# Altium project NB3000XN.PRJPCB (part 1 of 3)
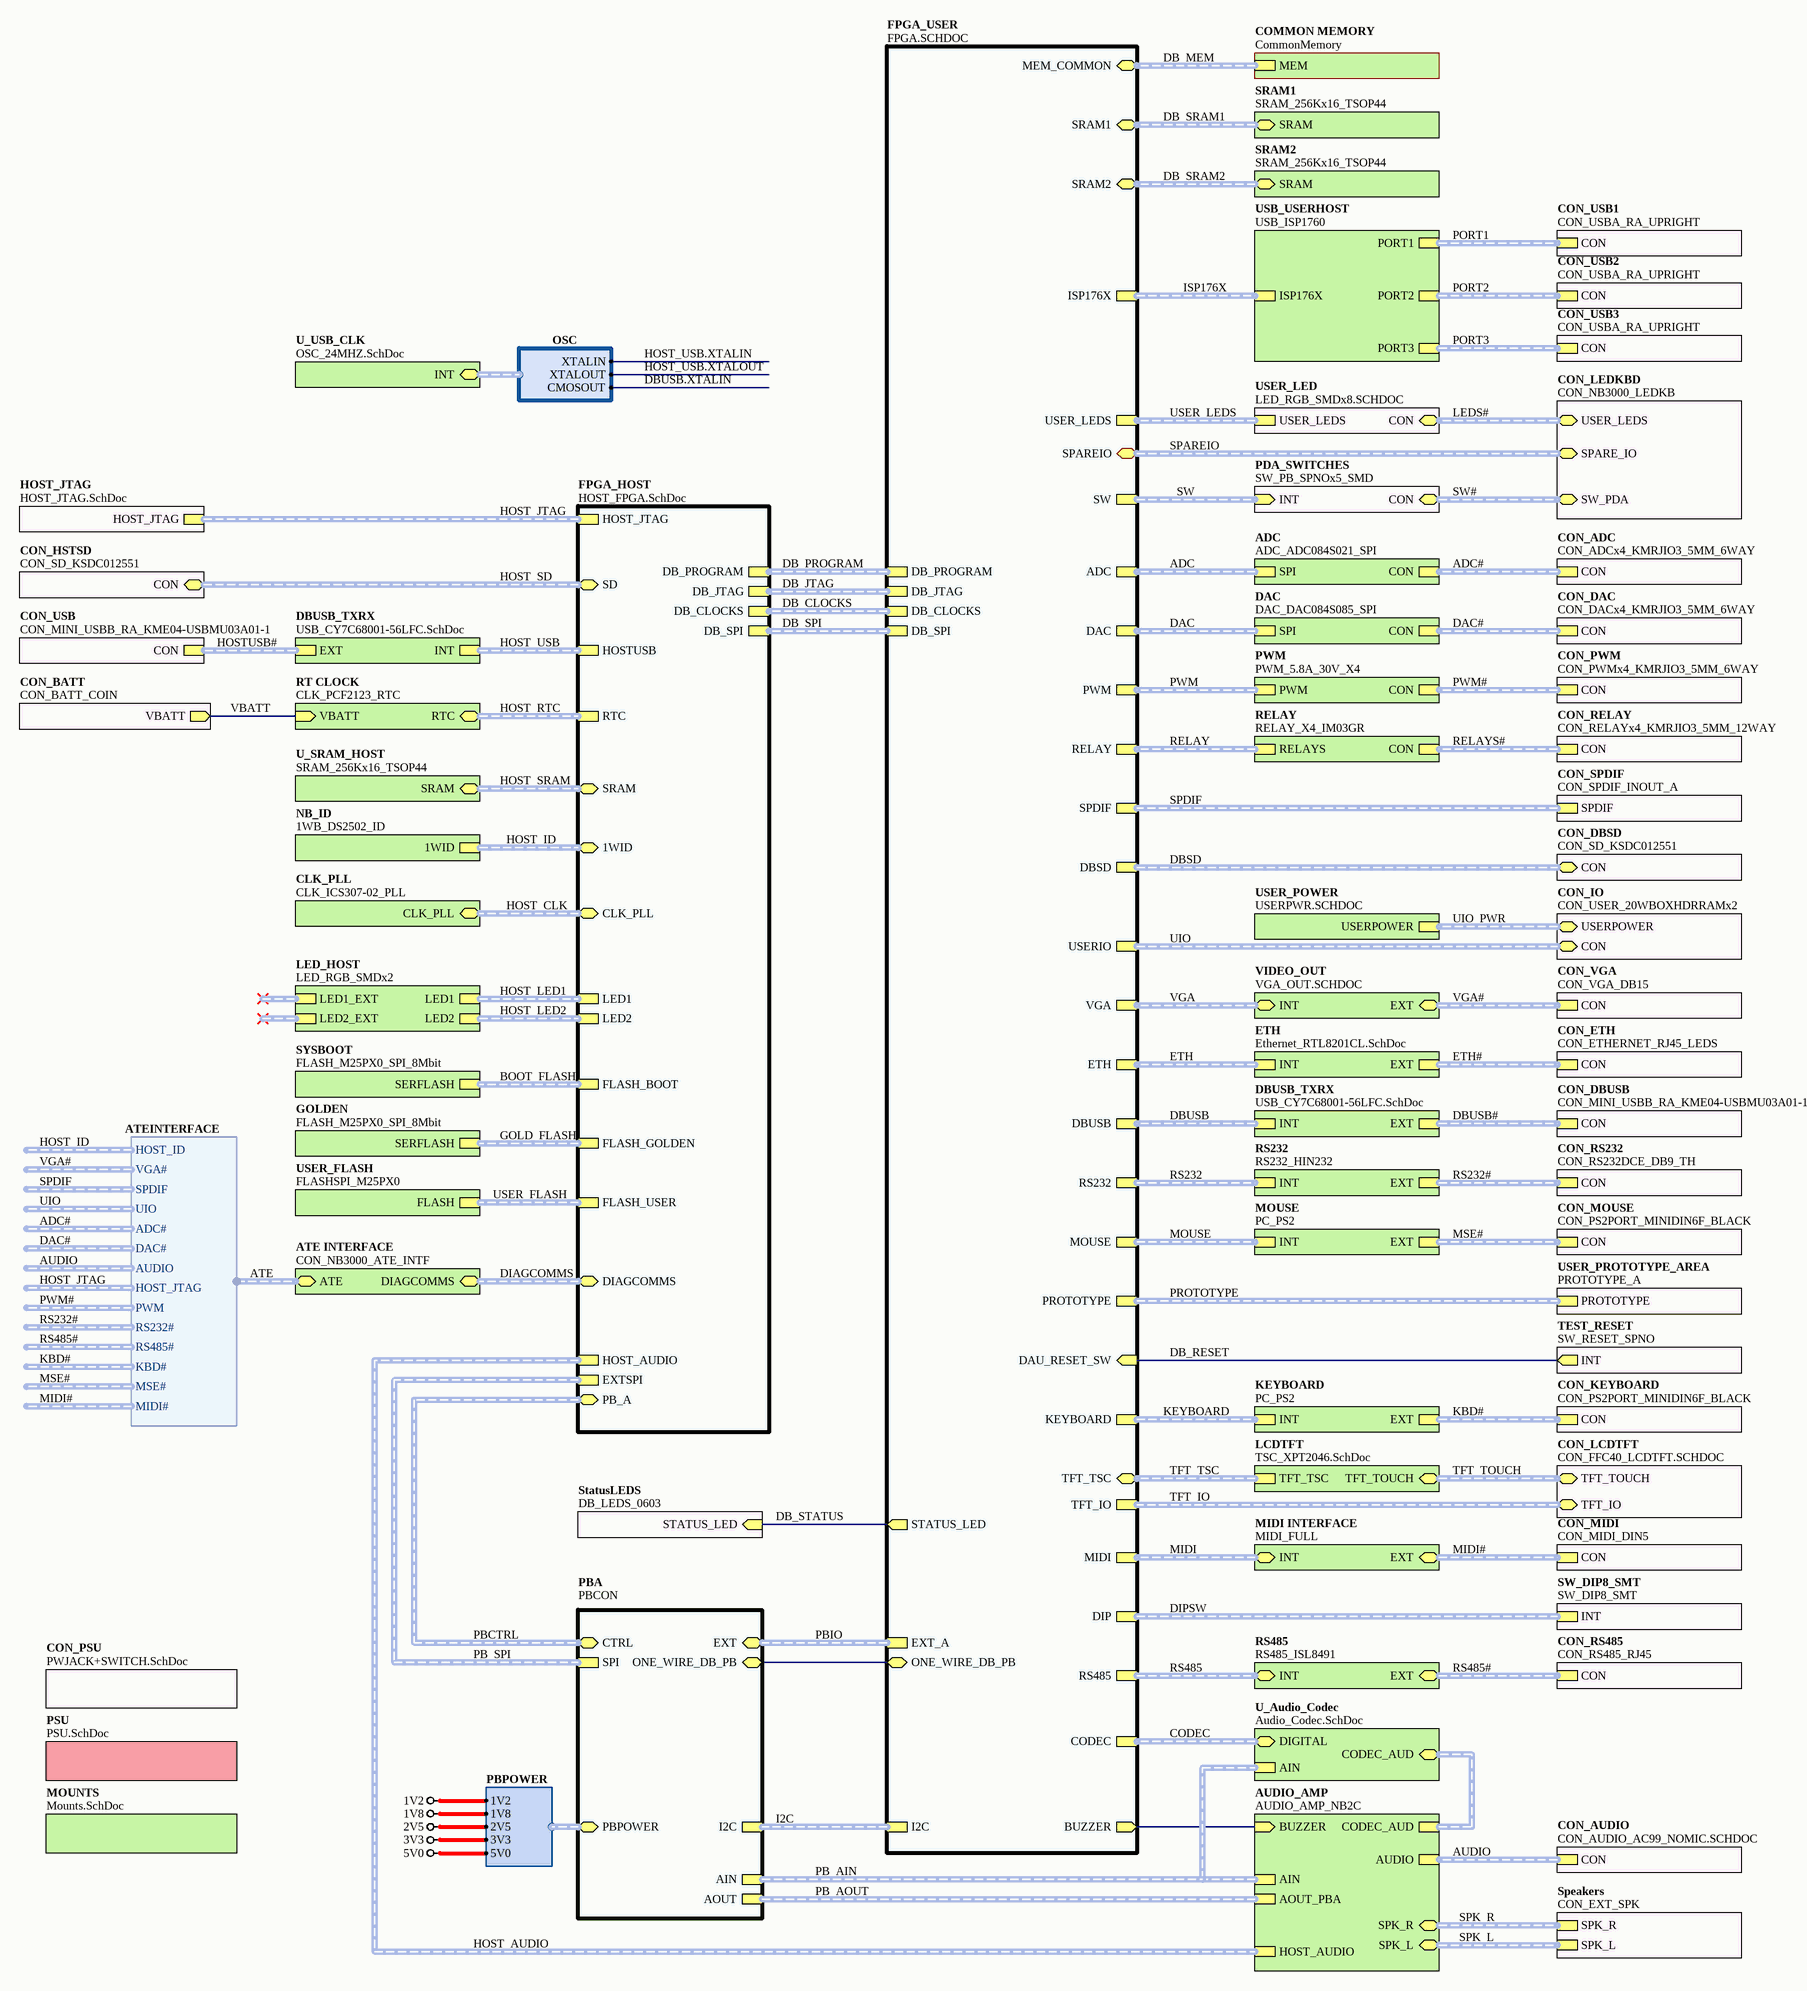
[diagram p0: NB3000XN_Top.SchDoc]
ProjectAddress1: 3 Minna Close; ProjectAddress2: Belrose; ProjectAddress3: NSW 2085; ProjectAddress4: Australia; ProjectAssyNum: TBA; ProjectOrganization: Altium Limited; ProjectRevision: 04; ProjectTitle: NB3000XN - Xilinx; ProjectTotalSheets: 106
22 sheets, 343 parts. Net scope: hierarchical (ports join the sheet entries above them; power ports are global).
Board files: NB3000XN.PcbDoc, NB3000XN_Panel.PcbDoc
Sheets:
  NB3000XN_Top.SchDoc
    PSU = PSU.SchDoc
    FPGA_USER = FPGA.SCHDOC
      U_FPGA_Power = FPGA_NonIO.SchDoc
      USER_DECOUPLING_CAPS_1V2 = FPGA_Bypass_1V2.SCHDOC
      USER_DECOUPLING_CAPS_3V3 = FPGA_Bypass_3V3.SCHDOC
    VIDEO_OUT = VGA_OUT.SCHDOC
      U_VIDEO_DAC = VIDEO_DAC_THS8134B.SchDoc
    FPGA_HOST = Host_FPGA.SchDoc
      HOST_NonIO = HOST_FPGA_NonIO.SchDoc
      HOST_DECOUPLING_CAPS_1V2 = FPGA_Bypass_1V2.SCHDOC
      HOST_DECOUPLING_CAPS_3V3 = FPGA_Bypass_3V3.SCHDOC
    HOST_JTAG = HOST_JTAG.SchDoc
    DBUSB_TXRX = USB_CY7C68001-56LFC.SchDoc
    ETH = Ethernet_RTL8201CL.SchDoc
    LCDTFT = TSC_XPT2046.SchDoc
    USER_LED = LED_RGB_SMDx8.SCHDOC
    U_Audio_Codec = Audio_Codec.SchDoc
    CON_LCDTFT = CON_FFC40_LCDTFT.SCHDOC
    MOUNTS = Mounts.SchDoc
    CON_PSU = PWJACK+SWITCH.SchDoc
    DBUSB_TXRX = USB_CY7C68001-56LFC.SchDoc
    USER_POWER = USERPWR.SchDoc
    CON_AUDIO = CON_AUDIO_AC99_NOMIC.SchDoc
    U_USB_CLK = OSC_24MHZ.SchDoc

## Sheet NB3000XN_Top.SchDoc: NB3000XN Top Level
size A2; Revision: 5; SheetNumber: 1; SheetTotal: 106; Organization: Altium Limited.; Address1: Level 3, 12a Rodborough Rd; Address2: Frenchs Forest 2086; Address3: NSW; Address4: AUSTRALIA

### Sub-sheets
ADC = ADC_ADC084S021_SPI (file not in this document): SPI (harness ADC_SPI), CON (harness ADC_CON)
ATE INTERFACE = CON_NB3000_ATE_INTF (file not in this document): ATE (harness ATEINTERFACE), DIAGCOMMS (harness DIAGCOMMS)
AUDIO_AMP = AUDIO_AMP_NB2C (file not in this document): BUZZER (in), CODEC_AUD (harness STEREO), AUDIO (harness AUDIO_EXT), SPK_L (harness SPEAKER), SPK_R (harness SPEAKER), HOST_AUDIO (harness STEREO), AIN (harness AUDIO_IN), AOUT_PBA (harness AUDIO_OUT)
CLK_PLL = CLK_ICS307-02_PLL (file not in this document): CLK_PLL (harness CLK_PLL)
COMMON MEMORY = CommonMemory (file not in this document): MEM (harness HOSTMEMORY)
CON_ADC = CON_ADCx4_KMRJIO3_5MM_6WAY (file not in this document): CON (harness ADC_CON)
CON_AUDIO = CON_AUDIO_AC99_NOMIC.SCHDOC: CON (harness AUDIO_EXT)
CON_BATT = CON_BATT_COIN (file not in this document): VBATT (out)
CON_DAC = CON_DACx4_KMRJIO3_5MM_6WAY (file not in this document): CON (harness DAC_CON)
CON_DBSD = CON_SD_KSDC012551 (file not in this document): CON (harness SD)
CON_DBUSB = CON_MINI_USBB_RA_KME04-USBMU03A01-1 (file not in this document): CON (harness USB_CON)
CON_ETH = CON_ETHERNET_RJ45_LEDS (file not in this document): CON (harness ETHERNET_CON)
CON_HSTSD = CON_SD_KSDC012551 (file not in this document): CON (harness SD)
CON_IO = CON_USER_20WBOXHDRRAMx2 (file not in this document): CON (harness IO36), USERPOWER (harness USERPOWER)
CON_KEYBOARD = CON_PS2PORT_MINIDIN6F_BLACK (file not in this document): CON (harness PS2)
CON_LCDTFT = CON_FFC40_LCDTFT.SCHDOC: TFT_IO (harness TFT_IO), TFT_TOUCH (harness TFT_TOUCH)
CON_LEDKBD = CON_NB3000_LEDKB (file not in this document): USER_LEDS (harness User_LEDS), SW_PDA (harness SW5), SPARE_IO (harness SPAREIO)
CON_MIDI = CON_MIDI_DIN5 (file not in this document): CON (harness MIDI_IO)
CON_MOUSE = CON_PS2PORT_MINIDIN6F_BLACK (file not in this document): CON (harness PS2)
CON_PSU = PWJACK+SWITCH.SchDoc: no entries
CON_PWM = CON_PWMx4_KMRJIO3_5MM_6WAY (file not in this document): CON (harness PWM_CON)
CON_RELAY = CON_RELAYx4_KMRJIO3_5MM_12WAY (file not in this document): CON (harness RELAY_CON4)
CON_RS232 = CON_RS232DCE_DB9_TH (file not in this document): CON (harness RS232_EXT)
CON_RS485 = CON_RS485_RJ45 (file not in this document): CON (harness RS485_EXT)
CON_SPDIF = CON_SPDIF_INOUT_A (file not in this document): SPDIF (harness SPDIF)
CON_USB = CON_MINI_USBB_RA_KME04-USBMU03A01-1 (file not in this document): CON (harness USB_CON)
CON_USB1 = CON_USBA_RA_UPRIGHT (file not in this document): CON (harness USB_CON)
CON_USB2 = CON_USBA_RA_UPRIGHT (file not in this document): CON (harness USB_CON)
CON_USB3 = CON_USBA_RA_UPRIGHT (file not in this document): CON (harness USB_CON)
CON_VGA = CON_VGA_DB15 (file not in this document): CON (harness VGA_CON)
DAC = DAC_DAC084S085_SPI (file not in this document): SPI (harness DAC_SPI), CON (harness DAC_CON)
DBUSB_TXRX = USB_CY7C68001-56LFC.SchDoc: EXT (harness USB_CON), INT (harness USB_INTF)
DBUSB_TXRX = USB_CY7C68001-56LFC.SchDoc: EXT (harness USB_CON), INT (harness USB_INTF)
ETH = Ethernet_RTL8201CL.SchDoc: INT (harness Ethernet), EXT (harness ETHERNET_CON)
FPGA_HOST = HOST_FPGA.SchDoc: HOST_JTAG (harness HARDSOFT_JTAG), LED1 (harness RGB_LED), LED2 (harness RGB_LED), 1WID (harness 1W), DB_PROGRAM (harness DAU_CTRL), CLK_PLL (harness CLK_PLL), FLASH_BOOT (harness SERFLASH), HOSTUSB (harness USB_INTF), SRAM (harness SRAM-256Kx16), RTC (harness RTC), SD (harness SD), HOST_AUDIO (harness STEREO), DB_JTAG (harness HARDSOFT_JTAG), DB_CLOCKS (harness DB_CLOCKS), FLASH_USER (harness SERIALFLASH), DB_SPI (harness DB_SPI), PB_A (harness PBCTRL), EXTSPI (harness EXTSPI), FLASH_GOLDEN (harness SERFLASH), DIAGCOMMS (harness DIAGCOMMS)
FPGA_USER = FPGA.SCHDOC: SRAM1 (harness SRAM-256Kx16), SRAM2 (harness SRAM-256Kx16), MEM_COMMON (harness HOSTMEMORY), DAU_RESET_SW (in), BUZZER (out), ONE_WIRE_DB_PB (bidir), SW (harness SW5), DIP (harness SW8), USERIO (harness IO36), EXT_A (harness PBIO), RS232 (harness RS232_INT), KEYBOARD (harness PS2), MOUSE (harness PS2), TFT_IO (harness TFT_IO), DB_PROGRAM (harness DAU_CTRL), STATUS_LED (out), USER_LEDS (harness USER_LEDS), RELAY (harness RELAY4), I2C (harness I2C), CODEC (harness AUDIO_DIGITAL), VGA (harness VGA), ETH (harness Ethernet), DBSD (harness SD), DBUSB (harness USB_INTF), PWM (harness PWM4), SPDIF (harness SPDIF), DAC (harness DAC_SPI), ADC (harness ADC_SPI), RS485 (harness RS485_INT), MIDI (harness MIDI_INT), DB_JTAG (harness HARDSOFT_JTAG), DB_CLOCKS (harness DB_CLOCKS), DB_SPI (harness DB_SPI), ISP176X (harness ISP176X), PROTOTYPE (harness IO36), SPAREIO (harness SPAREIO), TFT_TSC (harness TFT_TSC)
GOLDEN = FLASH_M25PX0_SPI_8Mbit (file not in this document): SERFLASH (harness SERFLASH)
HOST_JTAG = HOST_JTAG.SchDoc: HOST_JTAG (harness HARDSOFT_JTAG)
KEYBOARD = PC_PS2 (file not in this document): EXT (harness PS2), INT (harness PS2)
LCDTFT = TSC_XPT2046.SchDoc: TFT_TSC (harness TFT_TSC), TFT_TOUCH (harness TFT_TOUCH)
LED_HOST = LED_RGB_SMDx2 (file not in this document): LED1 (harness RGB_LED), LED2 (harness RGB_LED), LED1_EXT (harness RGB_LED), LED2_EXT (harness RGB_LED)
MIDI INTERFACE = MIDI_FULL (file not in this document): INT (harness MIDI_INT), EXT (harness MIDI_IO)
MOUNTS = Mounts.SchDoc: no entries
MOUSE = PC_PS2 (file not in this document): EXT (harness PS2), INT (harness PS2)
NB_ID = 1WB_DS2502_ID (file not in this document): 1WID (harness 1W)
PBA = PBCON (file not in this document): EXT (harness PBIO), ONE_WIRE_DB_PB (bidir), AIN (harness AUDIO_IN), I2C (harness I2C), SPI (harness EXTSPI), AOUT (harness AUDIO_OUT), CTRL (harness PBCTRL), PBPOWER (harness PBPOWER)
PDA_SWITCHES = SW_PB_SPNOx5_SMD (file not in this document): INT (harness SW5), CON (harness SW5)
PSU = PSU.SchDoc: no entries
PWM = PWM_5.8A_30V_X4 (file not in this document): PWM (harness PWM4), CON (harness PWM_CON)
RELAY = RELAY_X4_IM03GR (file not in this document): RELAYS (harness RELAY4), CON (harness RELAY_CON4)
RS232 = RS232_HIN232 (file not in this document): INT (harness RS232_INT), EXT (harness RS232_EXT)
RS485 = RS485_ISL8491 (file not in this document): INT (harness RS485_INT), EXT (harness RS485_EXT)
RT CLOCK = CLK_PCF2123_RTC (file not in this document): VBATT (in), RTC (harness RTC)
Speakers = CON_EXT_SPK (file not in this document): SPK_L (harness SPEAKER), SPK_R (harness SPEAKER)
SRAM1 = SRAM_256Kx16_TSOP44 (file not in this document): SRAM (harness SRAM-256Kx16)
SRAM2 = SRAM_256Kx16_TSOP44 (file not in this document): SRAM (harness SRAM-256Kx16)
StatusLEDS = DB_LEDS_0603 (file not in this document): STATUS_LED (in)
SW_DIP8_SMT = SW_DIP8_SMT (file not in this document): INT (harness SW8)
SYSBOOT = FLASH_M25PX0_SPI_8Mbit (file not in this document): SERFLASH (harness SERFLASH)
TEST_RESET = SW_RESET_SPNO (file not in this document): INT (out)
U_Audio_Codec = Audio_Codec.SchDoc: DIGITAL (harness AUDIO_DIGITAL), CODEC_AUD (harness STEREO), AIN (harness AUDIO_IN)
U_SRAM_HOST = SRAM_256Kx16_TSOP44 (file not in this document): SRAM (harness SRAM-256Kx16)
U_USB_CLK = OSC_24MHZ.SchDoc: INT (harness OSC)
USB_USERHOST = USB_ISP1760 (file not in this document): ISP176X (harness ISP176X), PORT1 (harness USB_CON), PORT2 (harness USB_CON), PORT3 (harness USB_CON)
USER_FLASH = FLASHSPI_M25PX0 (file not in this document): FLASH (harness SERIALFLASH)
USER_LED = LED_RGB_SMDx8.SCHDOC: USER_LEDS (harness USER_LEDS), CON (harness UseR_LEDS)
USER_POWER = USERPWR.SCHDOC: USERPOWER (harness USERPOWER)
USER_PROTOTYPE_AREA = PROTOTYPE_A (file not in this document): PROTOTYPE (harness IO36)
VIDEO_OUT = VGA_OUT.SCHDOC: INT (harness VGA), EXT (harness VGA_CON)

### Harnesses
PBPOWER: 1V2, 1V8, 2V5, 3V3, 5V0
ATEINTERFACE: VGA#, SPDIF, UIO, ADC#, DAC#, AUDIO, HOST_JTAG, PWM, RS232#, RS485#, KBD#, MSE#, MIDI#, HOST_ID
OSC: CMOSOUT, XTALIN, XTALOUT

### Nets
BUZZER: sheet FPGA_USER/BUZZER, sheet AUDIO_AMP/BUZZER
DB_RESET: sheet FPGA_USER/DAU_RESET_SW, sheet TEST_RESET/INT
DB_STATUS: sheet StatusLEDS/STATUS_LED, sheet FPGA_USER/STATUS_LED  [project net DB_PROGRAM.DONE]
ONE_WIRE_DB_PB: sheet FPGA_USER/ONE_WIRE_DB_PB, sheet PBA/ONE_WIRE_DB_PB
VBATT: sheet CON_BATT/VBATT, sheet RT CLOCK/VBATT

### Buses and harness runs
harness ADC = sheet ADC/SPI = sheet FPGA_USER/ADC
harness ADC# = sheet ADC/CON = sheet CON_ADC/CON
harness ATE = sheet ATE INTERFACE/ATE
harness AUDIO = sheet AUDIO_AMP/AUDIO = sheet CON_AUDIO/CON
harness BOOT_FLASH = sheet FPGA_HOST/FLASH_BOOT = sheet SYSBOOT/SERFLASH
harness CODEC = sheet FPGA_USER/CODEC = sheet U_Audio_Codec/DIGITAL
harness DAC = sheet DAC/SPI = sheet FPGA_USER/DAC
harness DAC# = sheet CON_DAC/CON = sheet DAC/CON
harness DB_CLOCKS = sheet FPGA_HOST/DB_CLOCKS = sheet FPGA_USER/DB_CLOCKS
harness DB_JTAG = sheet FPGA_HOST/DB_JTAG = sheet FPGA_USER/DB_JTAG
harness DB_MEM = sheet COMMON MEMORY/MEM = sheet FPGA_USER/MEM_COMMON
harness DB_PROGRAM = sheet FPGA_HOST/DB_PROGRAM = sheet FPGA_USER/DB_PROGRAM
harness DB_SPI = sheet FPGA_HOST/DB_SPI = sheet FPGA_USER/DB_SPI
harness DB_SRAM1 = sheet FPGA_USER/SRAM1 = sheet SRAM1/SRAM
harness DB_SRAM2 = sheet FPGA_USER/SRAM2 = sheet SRAM2/SRAM
harness DBSD = sheet CON_DBSD/CON = sheet FPGA_USER/DBSD
harness DBUSB = sheet DBUSB_TXRX/INT = sheet FPGA_USER/DBUSB
harness DBUSB# = sheet CON_DBUSB/CON = sheet DBUSB_TXRX/EXT
harness DIAGCOMMS = sheet ATE INTERFACE/DIAGCOMMS = sheet FPGA_HOST/DIAGCOMMS
harness DIPSW = sheet FPGA_USER/DIP = sheet SW_DIP8_SMT/INT
harness ETH = sheet ETH/INT = sheet FPGA_USER/ETH
harness ETH# = sheet CON_ETH/CON = sheet ETH/EXT
harness GOLD_FLASH = sheet FPGA_HOST/FLASH_GOLDEN = sheet GOLDEN/SERFLASH
harness HOST_AUDIO = sheet AUDIO_AMP/HOST_AUDIO = sheet FPGA_HOST/HOST_AUDIO
harness HOST_CLK = sheet CLK_PLL/CLK_PLL = sheet FPGA_HOST/CLK_PLL
harness HOST_ID = sheet FPGA_HOST/1WID = sheet NB_ID/1WID
harness HOST_JTAG = sheet FPGA_HOST/HOST_JTAG = sheet HOST_JTAG/HOST_JTAG
harness HOST_LED1 = sheet FPGA_HOST/LED1 = sheet LED_HOST/LED1
harness HOST_LED2 = sheet FPGA_HOST/LED2 = sheet LED_HOST/LED2
harness HOST_RTC = sheet FPGA_HOST/RTC = sheet RT CLOCK/RTC
harness HOST_SD = sheet CON_HSTSD/CON = sheet FPGA_HOST/SD
harness HOST_SRAM = sheet FPGA_HOST/SRAM = sheet U_SRAM_HOST/SRAM
harness HOST_USB = sheet DBUSB_TXRX/INT = sheet FPGA_HOST/HOSTUSB
harness HOSTUSB# = sheet CON_USB/CON = sheet DBUSB_TXRX/EXT
harness I2C = sheet FPGA_USER/I2C = sheet PBA/I2C
harness ISP176X = sheet FPGA_USER/ISP176X = sheet USB_USERHOST/ISP176X
harness KBD# = sheet CON_KEYBOARD/CON = sheet KEYBOARD/EXT
harness KEYBOARD = sheet FPGA_USER/KEYBOARD = sheet KEYBOARD/INT
harness LEDS# = sheet CON_LEDKBD/USER_LEDS = sheet USER_LED/CON
harness MIDI = sheet FPGA_USER/MIDI = sheet MIDI INTERFACE/INT
harness MIDI# = sheet CON_MIDI/CON = sheet MIDI INTERFACE/EXT
harness MOUSE = sheet FPGA_USER/MOUSE = sheet MOUSE/INT
harness MSE# = sheet CON_MOUSE/CON = sheet MOUSE/EXT
harness PB_AIN = sheet AUDIO_AMP/AIN = sheet PBA/AIN = sheet U_Audio_Codec/AIN
harness PB_AOUT = sheet AUDIO_AMP/AOUT_PBA = sheet PBA/AOUT
harness PB_SPI = sheet FPGA_HOST/EXTSPI = sheet PBA/SPI
harness PBCTRL = sheet FPGA_HOST/PB_A = sheet PBA/CTRL
harness PBIO = sheet FPGA_USER/EXT_A = sheet PBA/EXT
harness PORT1 = sheet CON_USB1/CON = sheet USB_USERHOST/PORT1
harness PORT2 = sheet CON_USB2/CON = sheet USB_USERHOST/PORT2
harness PORT3 = sheet CON_USB3/CON = sheet USB_USERHOST/PORT3
harness PROTOTYPE = sheet FPGA_USER/PROTOTYPE = sheet USER_PROTOTYPE_AREA/PROTOTYPE
harness PWM = sheet FPGA_USER/PWM = sheet PWM/PWM
harness PWM# = sheet CON_PWM/CON = sheet PWM/CON
harness RELAY = sheet FPGA_USER/RELAY = sheet RELAY/RELAYS
harness RELAYS# = sheet CON_RELAY/CON = sheet RELAY/CON
harness RS232 = sheet FPGA_USER/RS232 = sheet RS232/INT
harness RS232# = sheet CON_RS232/CON = sheet RS232/EXT
harness RS485 = sheet FPGA_USER/RS485 = sheet RS485/INT
harness RS485# = sheet CON_RS485/CON = sheet RS485/EXT
harness sheet AUDIO_AMP/CODEC_AUD = sheet U_Audio_Codec/CODEC_AUD
harness SPAREIO = sheet CON_LEDKBD/SPARE_IO = sheet FPGA_USER/SPAREIO
harness SPDIF = sheet CON_SPDIF/SPDIF = sheet FPGA_USER/SPDIF
harness SPK_L = sheet AUDIO_AMP/SPK_L = sheet Speakers/SPK_L
harness SPK_R = sheet AUDIO_AMP/SPK_R = sheet Speakers/SPK_R
harness SW = sheet FPGA_USER/SW = sheet PDA_SWITCHES/INT
harness SW# = sheet CON_LEDKBD/SW_PDA = sheet PDA_SWITCHES/CON
harness TFT_IO = sheet CON_LCDTFT/TFT_IO = sheet FPGA_USER/TFT_IO
harness TFT_TOUCH = sheet CON_LCDTFT/TFT_TOUCH = sheet LCDTFT/TFT_TOUCH
harness TFT_TSC = sheet FPGA_USER/TFT_TSC = sheet LCDTFT/TFT_TSC
harness UIO = sheet CON_IO/CON = sheet FPGA_USER/USERIO
harness UIO_PWR = sheet CON_IO/USERPOWER = sheet USER_POWER/USERPOWER
harness USER_FLASH = sheet FPGA_HOST/FLASH_USER = sheet USER_FLASH/FLASH
harness USER_LEDS = sheet FPGA_USER/USER_LEDS = sheet USER_LED/USER_LEDS
harness VGA = sheet FPGA_USER/VGA = sheet VIDEO_OUT/INT
harness VGA# = sheet CON_VGA/CON = sheet VIDEO_OUT/EXT

## Sheet PSU.SchDoc: NB3000 POWER SUPPLIES
size A4; Organization: Altium Limited.; Address1: 3 Minna Close; Address2: Belrose; Address3: NSW 2085; Address4: AUSTRALIA; DocumentNumber: 7; Revision: 6; SheetNumber: 8; SheetTotal: 78
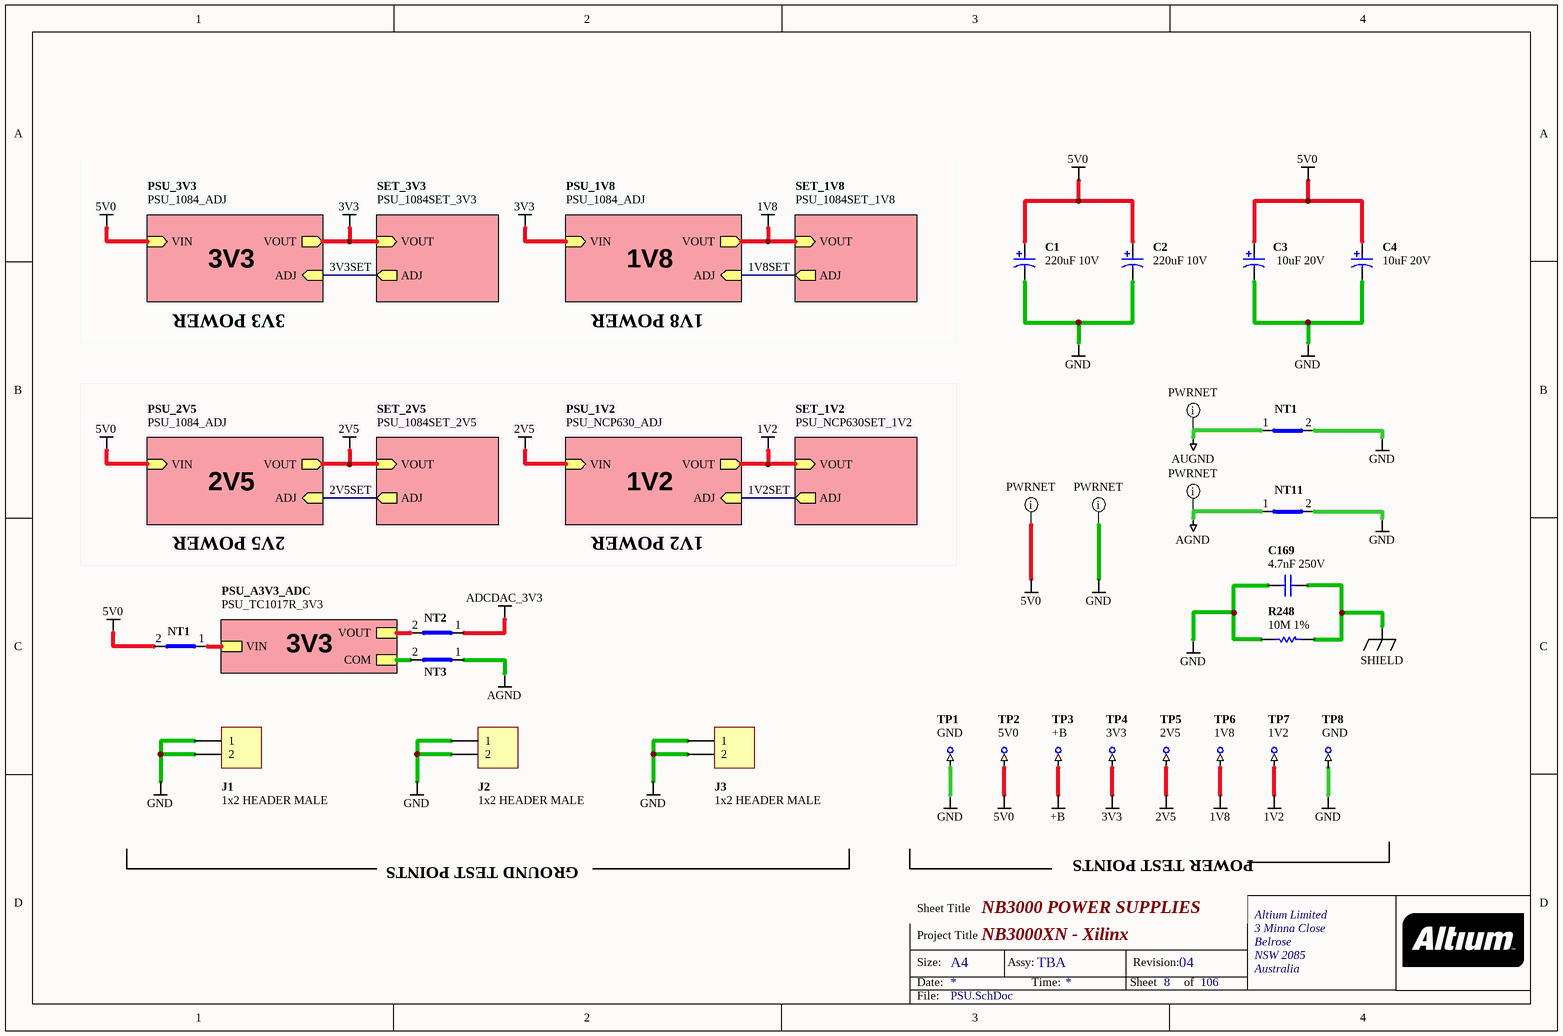
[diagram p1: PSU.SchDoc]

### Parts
(Parts that share a designator on the sheet are numbered #1, #2 ... from top to bottom, then left to right.)
C1#1  220uF 10V  [CAPC7343-STAR]
C2#1  220uF 10V  [CAPC7343-STAR]
C3#1  10uF 20V  [CAPC3528-STAR]
C4#1  10uF 20V  [CAPC3528-STAR]
C169  4.7nF 250V  [CAPM7163]
J1#1  1x2 HEADER MALE  [HDR1X2]
J2  1x2 HEADER MALE  [HDR1X2]
J3#1  1x2 HEADER MALE  [HDR1X2]
NT1#1  Net Tie SMT2  [NETTIE-SMT2-31X39]  (value not drawn)  (net tie, no BOM)
NT1#2  Net Tie SMT2  [NETTIE-SMT2-31X51]  (value not drawn)  (net tie, no BOM)
NT2#1  Net Tie SMT2  [NETTIE-SMT2-31X51]  (value not drawn)  (net tie, no BOM)
NT3#1  Net Tie SMT2  [NETTIE-SMT2-31X51]  (value not drawn)  (net tie, no BOM)
NT11#1  Net Tie SMT2  [NETTIE-SMT2-31X39]  (value not drawn)  (net tie, no BOM)
R248  10M 1%  [RESC3216]
TP1  GND  [TestPin]  (no BOM)
TP2  5V0  [TestPin]  (no BOM)
TP3  +B  [TestPin]  (no BOM)
TP4  3V3  [TestPin]  (no BOM)
TP5  2V5  [TestPin]  (no BOM)
TP6  1V8  [TestPin]  (no BOM)
TP7  1V2  [TestPin]  (no BOM)
TP8  GND  [TestPin]  (no BOM)

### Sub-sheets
PSU_1V2 = PSU_NCP630_ADJ (file not in this document): VIN (in), VOUT (out), ADJ (in)
PSU_1V8 = PSU_1084_ADJ (file not in this document): VIN (in), VOUT (out), ADJ (in)
PSU_2V5 = PSU_1084_ADJ (file not in this document): VIN (in), VOUT (out), ADJ (in)
PSU_3V3 = PSU_1084_ADJ (file not in this document): VIN (in), VOUT (out), ADJ (in)
PSU_A3V3_ADC = PSU_TC1017R_3V3 (file not in this document): VIN, VOUT, COM
SET_1V2 = PSU_NCP630SET_1V2 (file not in this document): VOUT (in), ADJ (out)
SET_1V8 = PSU_1084SET_1V8 (file not in this document): VOUT (in), ADJ (out)
SET_2V5 = PSU_1084SET_2V5 (file not in this document): VOUT (in), ADJ (out)
SET_3V3 = PSU_1084SET_3V3 (file not in this document): VOUT (in), ADJ (out)

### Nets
1V2: TP7.1 ; sheet PSU_1V2/VOUT, sheet SET_1V2/VOUT
1V8: TP6.1 ; sheet PSU_1V8/VOUT, sheet SET_1V8/VOUT
2V5: TP5.1 ; sheet PSU_1V2/VIN, sheet PSU_2V5/VOUT, sheet SET_2V5/VOUT
3V3: TP4.1 ; sheet PSU_1V8/VIN, sheet PSU_3V3/VOUT, sheet SET_3V3/VOUT
5V0: C1#1.1 C2#1.1 C3#1.1 C4#1.1 NT1#2.2(Net2) TP2.1 ; sheet PSU_2V5/VIN, sheet PSU_3V3/VIN
+B: TP3.1
ADCDAC_3V3: NT2#1.1(Net1)
AGND: NT3#1.1(Net1) NT11#1.1(Net1)
AUGND: NT1#1.1(Net1)
GND: C1#1.2 C2#1.2 C3#1.2 C4#1.2 C169.2 J1#1.1 J1#1.2 J2.1 J2.2 J3#1.1 J3#1.2 NT1#1.2(Net2) NT11#1.2(Net2) R248.2 TP1.1 TP8.1
SHIELD: C169.1 R248.1
1V2SET: sheet PSU_1V2/ADJ, sheet SET_1V2/ADJ
1V8SET: sheet PSU_1V8/ADJ, sheet SET_1V8/ADJ
2V5SET: sheet PSU_2V5/ADJ, sheet SET_2V5/ADJ
3V3SET: sheet PSU_3V3/ADJ, sheet SET_3V3/ADJ
NetNT1#2_1: NT1#2.1(Net1) ; sheet PSU_A3V3_ADC/VIN
NetNT2#1_2: NT2#1.2(Net2) ; sheet PSU_A3V3_ADC/VOUT
NetNT3#1_2: NT3#1.2(Net2) ; sheet PSU_A3V3_ADC/COM

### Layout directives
net class PWRNET: 5V0, AGND, AUGND, GND

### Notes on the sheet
- 3V3
- 3V3 POWER
- 1V8
- 1V8 POWER
- 2V5
- 1V2
- 2V5 POWER
- 1V2 POWER
- POWER TEST POINTS
- GROUND TEST POINTS

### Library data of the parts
C1#1 C2#1 = D-101-0088: Capacitor, Tantalum, 220uF 10% 10V MCCT-D (7343-31); Polarity: Polarized
C3#1 C4#1 = D-101-0007: Capacitor, Tantalum, 10uF 10% 20V MCCT-B (3528); Polarity: Polarized
C169 = D-101-0019: Capacitor, Ceramic, 4.7nF 20% 250V Panasonic BC J Lead (CAPM7163) Y5V; Polarity: Non-Polarized; Tolerance: 20% %
J1#1 J2 J3#1 = D-300-0020: Header IDC, 2 x 1 Pin Vertical 2.54mm Pitch (Non-Boxed, Male); Max Current: 3 A
NT1#1 NT11#1 = D-002-0004: Net-Tie, Surface Mount, 2 x 2.0mm x 0.8mm SMT Pads - For 0.8mm Track
NT1#2 NT2#1 NT3#1 = D-002-0003: Net-Tie, Surface Mount, 2 x 1.6mm x 0.8mm SMT Pads - For 0.8mm Track
R248 = D-100-0059: Resistor, 10M 1%1206 (3216); Power Rating: 250 mW
TP1-TP8 = D-006-0000: Test Point, PCB Mount with Silkscreen Box

## Sheet FPGA.SCHDOC: USER FPGA Connections
size A2; Organization: Altium Limited.; Address1: Level 3, 12a Rodborough Rd; Address2: Frenchs Forest 2086; Address3: NSW; Address4: AUSTRALIA; DocumentNumber: 9; SheetNumber: 10; SheetTotal: 78; PageSetup: Record=PageOptions|CenterHorizontal=True|CenterVertical=True|PrintScale=0.50|XCorrection=1.00|YCorrection=1.00|PrintKind=0|BorderSize=5000000|LeftOffset=0|BottomOffset=0|Orientation=2|PaperLength=4199|PaperWidth=2969|Scale=100|PaperSource=7|PrintQuality=600|MediaType=1|DitherType=10|PaperKind=A3 (297 x 420 mm)|PrintScaleMode=1
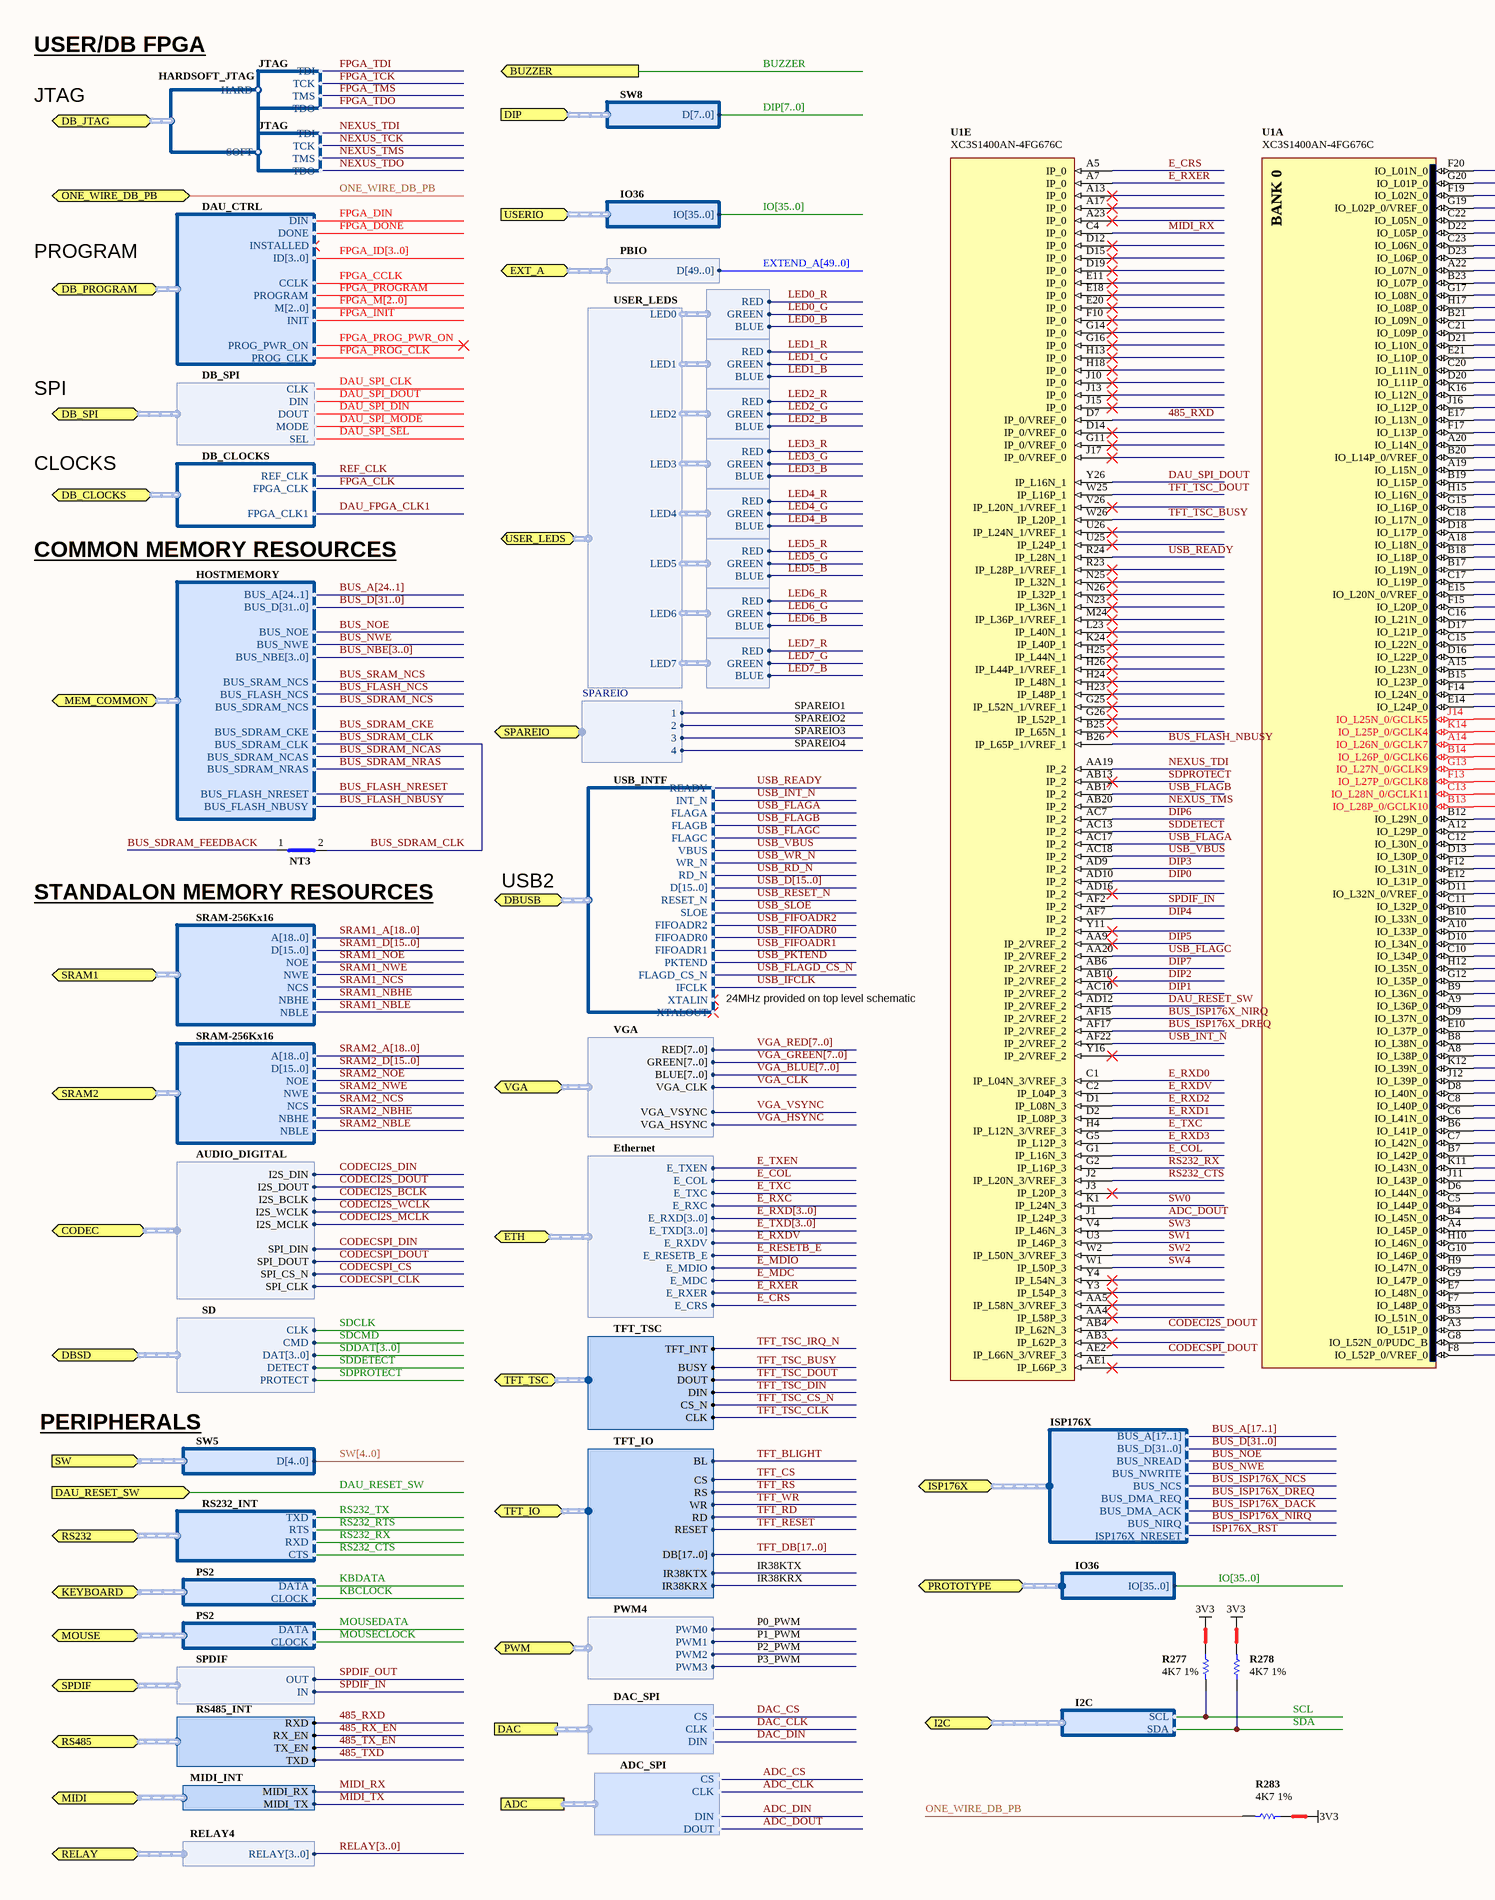
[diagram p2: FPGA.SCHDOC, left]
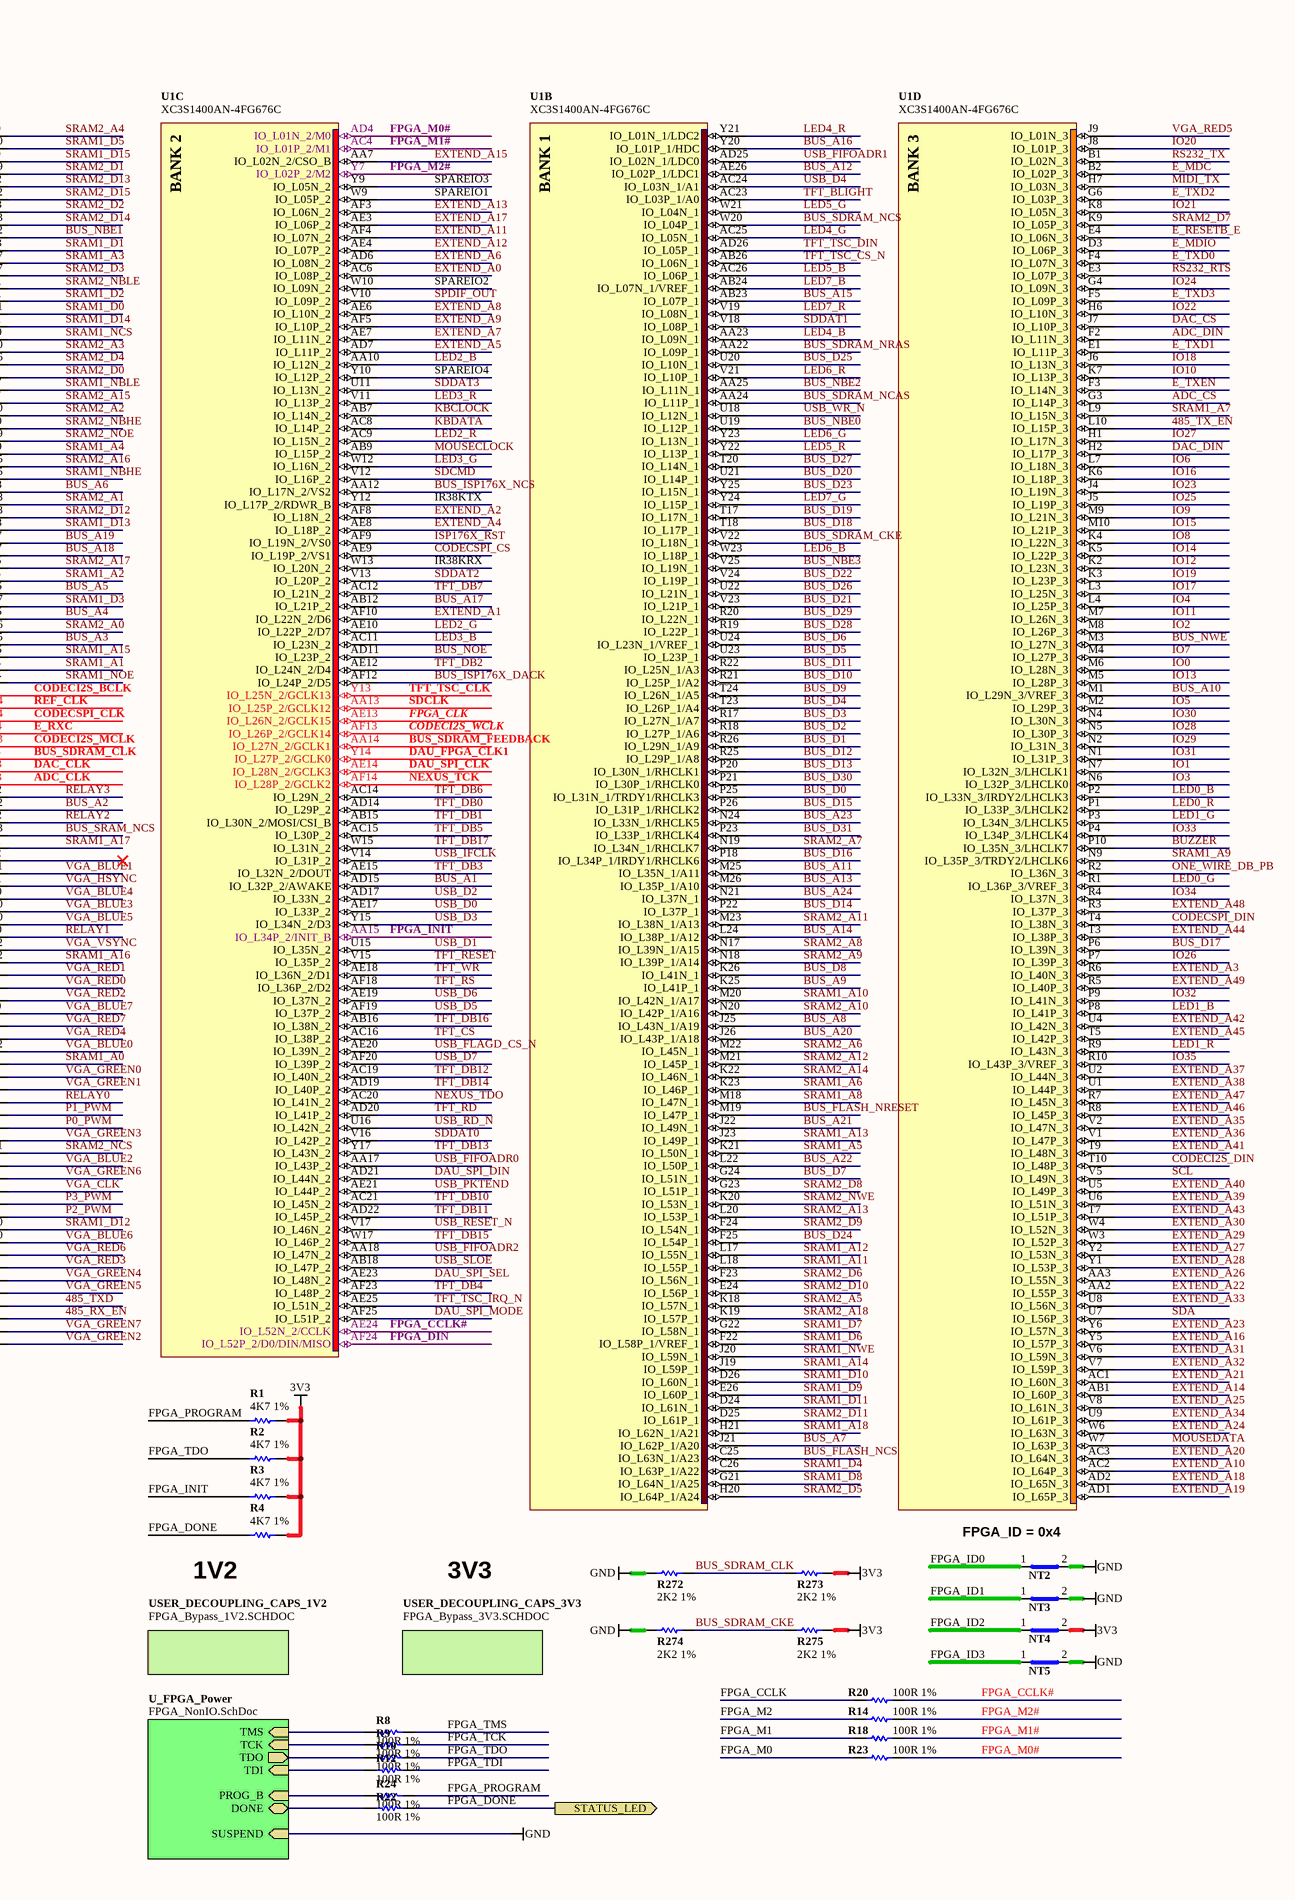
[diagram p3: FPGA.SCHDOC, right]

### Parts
(Parts that share a designator on the sheet are numbered #1, #2 ... from top to bottom, then left to right.)
NT2#2  Net Tie SMT2  [NETTIE-SMT2-8X8]  (value not drawn)  (net tie, no BOM)
NT3#2  Net Tie SMT2  [NETTIE-SMT2-8X8]  (value not drawn)  (net tie, no BOM)
NT3#3  Net Tie SMT2  [NETTIE-SMT2-8X8]  (value not drawn)  (net tie, no BOM)
NT4  Net Tie SMT2  [NETTIE-SMT2-8X8]  (value not drawn)  (net tie, no BOM)
NT5  Net Tie SMT2  [NETTIE-SMT2-8X8]  (value not drawn)  (net tie, no BOM)
R1#1  4K7 1%  [RESC1005-STAR]
R2#1  4K7 1%  [RESC1005-STAR]
R3#1  4K7 1%  [RESC1005-STAR]
R4#1  4K7 1%  [RESC1005-STAR]
R8#1  100R 1%  [RESC1005-STAR]
R9#1  100R 1%  [RESC1005-STAR]
R10#1  100R 1%  [RESC1005-STAR]
R12#1  100R 1%  [RESC1005-STAR]
R14#1  100R 1%  [RESC1005-STAR]
R18#1  100R 1%  [RESC1005-STAR]
R20#1  100R 1%  [RESC1005-STAR]
R22#1  100R 1%  [RESC1005-STAR]
R23#1  100R 1%  [RESC1005-STAR]
R24#1  100R 1%  [RESC1005-STAR]
R272  2K2 1%  [RESC1005-STAR]
R273  2K2 1%  [RESC1005-STAR]
R274  2K2 1%  [RESC1005-STAR]
R275  2K2 1%  [RESC1005-STAR]
R277  4K7 1%  [RESC1005-STAR]
R278  4K7 1%  [RESC1005-STAR]
R283  4K7 1%  [RESC1005-STAR]
U1#1  XC3S1400AN-4FG676C  [BGA100P26X26-676]  (parts A,B,C,D,E of 9)

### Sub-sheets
U_FPGA_Power = FPGA_NonIO.SchDoc: TMS (in), DONE (bidir), TCK (in), TDI (in), PROG_B (in), TDO (out), SUSPEND (in)
USER_DECOUPLING_CAPS_1V2 = FPGA_Bypass_1V2.SCHDOC: no entries
USER_DECOUPLING_CAPS_3V3 = FPGA_Bypass_3V3.SCHDOC: no entries

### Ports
ADC (harness ADC_SPI), BUZZER (out), CODEC (harness AUDIO_DIGITAL), DAC (harness DAC_SPI), DAU_RESET_SW (in), DB_CLOCKS (harness DB_CLOCKS), DB_JTAG (harness HARDSOFT_JTAG), DB_PROGRAM (harness DAU_CTRL), DB_SPI (harness DB_SPI), DBSD (harness SD), DBUSB (harness USB_INTF), DIP (harness SW8), ETH (harness Ethernet), EXT_A (harness PBIO), I2C (harness I2C), ISP176X (harness ISP176X), KEYBOARD (harness PS2), MEM_COMMON (harness HOSTMEMORY), MIDI (harness MIDI_INT), MOUSE (harness PS2), ONE_WIRE_DB_PB (bidir), PROTOTYPE (harness IO36), PWM (harness PWM4), RELAY (harness RELAY4), RS232 (harness RS232_INT), RS485 (harness RS485_INT), SPAREIO (harness SPAREIO), SPDIF (harness SPDIF), SRAM1 (harness SRAM-256Kx16), SRAM2 (harness SRAM-256Kx16), STATUS_LED (out), SW (harness SW5), TFT_IO (harness TFT_IO), TFT_TSC (harness TFT_TSC), USER_LEDS (harness USER_LEDS), USERIO (harness IO36), VGA (harness VGA)

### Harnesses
SRAM-256Kx16: A[18..0], D[15..0], NCS, NWE, NOE, NBHE, NBLE
HOSTMEMORY: BUS_A[24..1], BUS_D[31..0], BUS_NOE, BUS_NWE, BUS_NBE[3..0], BUS_SRAM_NCS, BUS_FLASH_NCS, BUS_SDRAM_NCS, BUS_SDRAM_CKE, BUS_SDRAM_CLK, BUS_SDRAM_NCAS, BUS_SDRAM_NRAS, BUS_FLASH_NRESET, BUS_FLASH_NBUSY
DAU_CTRL: DIN, DONE, INSTALLED, ID[3..0], CCLK, PROGRAM, M[2..0], INIT, PROG_PWR_ON, PROG_CLK
SW5: D[4..0]
PS2: DATA, CLOCK
RS232_INT: RXD, TXD, RTS, CTS
IO36: IO[35..0]
I2C: SCL, SDA
RGB_LED: GREEN, RED, BLUE
AUDIO_DIGITAL: I2S_DOUT, I2S_DIN, I2S_BCLK, I2S_WCLK, I2S_MCLK, SPI_CLK, SPI_DIN, SPI_DOUT, SPI_CS_N
SW8: D[7..0]
SD: CLK, CMD, DAT[3..0], DETECT, PROTECT
Ethernet: E_RXC, E_TXC, E_TXD[3..0], E_TXEN, E_COL, E_RXD[3..0], E_RXDV, E_RESETB_E, E_MDIO, E_MDC, E_RXER, E_CRS
SPDIF: IN, OUT
VGA: RED[7..0], GREEN[7..0], BLUE[7..0], VGA_CLK, VGA_VSYNC, VGA_HSYNC
RELAY4: RELAY[3..0]
ADC_SPI: CS, CLK, DIN, DOUT
DAC_SPI: CS, CLK, DIN
MIDI_INT: MIDI_TX, MIDI_RX
JTAG: TMS, TDO, TDI, TCK
HARDSOFT_JTAG: HARD, SOFT
DB_CLOCKS: REF_CLK, FPGA_CLK, FPGA_CLK1
PWM4: PWM0, PWM1, PWM2, PWM3
RS485_INT: TX_EN, RXD, RX_EN, TXD
DB_SPI: MODE, SEL, CLK, DIN, DOUT
TFT_IO: CS, RS, WR, RD, RESET, DB[17..0], BL, IR38KTX, IR38KRX
USER_LEDS: LED0, LED1, LED2, LED3, LED4, LED5, LED6, LED7
PBIO: D[49..0]
USB_INTF: READY, INT_N, SLOE, FIFOADR2, FIFOADR0, FIFOADR1, PKTEND, FLAGD_CS_N, FLAGA, FLAGB, FLAGC, WR_N, RD_N, D[15..0], RESET_N, IFCLK, XTALIN, VBUS, XTALOUT
ISP176X: BUS_A[17..1], BUS_D[31..0], BUS_NREAD, BUS_NCS, BUS_DMA_REQ, BUS_DMA_ACK, BUS_NIRQ, BUS_NWRITE, ISP176X_NRESET
SPAREIO: 1, 2, 3, 4
TFT_TSC: CLK, CS_N, DIN, DOUT, BUSY, TFT_INT

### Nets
3V3: NT4.2(Net2) R1#1.2 R2#1.2 R3#1.2 R4#1.2 R273.2 R275.2 R277.1 R278.2 R283.1
GND: NT2#2.2(Net2) NT3#3.2(Net2) NT5.2(Net2) R272.1 R274.1 ; sheet U_FPGA_Power/SUSPEND
485_RX_EN: U1#1.A3(IO_L51P_0) ; port RS485.RX_EN  [project net RS485.RX_EN]
485_RXD: U1#1.D7(IP_0/VREF_0) ; port RS485.RXD  [project net RS485.RXD]
485_TX_EN: U1#1.L10(IO_L15P_3) ; port RS485.TX_EN  [project net RS485.TX_EN]
485_TXD: U1#1.B3(IO_L51N_0) ; port RS485.TXD  [project net RS485.TXD]
ADC_CLK: U1#1.B13(IO_L28P_0/GCLK10) ; port ADC.CLK  [project net ADC.CLK]
ADC_CS: U1#1.G3(IO_L14P_3) ; port ADC.CS  [project net ADC.CS]
ADC_DIN: U1#1.F2(IO_L11N_3) ; port ADC.DIN  [project net ADC.DIN]
ADC_DOUT: U1#1.J1(IP_L24P_3) ; port ADC.DOUT  [project net ADC.DOUT]
BUS_A1: U1#1.AD15(IO_L32P_2/AWAKE)
BUS_A2: U1#1.A12(IO_L29P_0)
BUS_A3: U1#1.A15(IO_L23N_0)
BUS_A4: U1#1.C15(IO_L22N_0)
BUS_A5: U1#1.C16(IO_L21N_0)
BUS_A6: U1#1.C18(IO_L17N_0)
BUS_A7: U1#1.J21(IO_L62P_1/A20)
BUS_A8: U1#1.J25(IO_L43N_1/A19)
BUS_A9: U1#1.K25(IO_L41P_1)
BUS_A10: U1#1.M1(IO_L29N_3/VREF_3)
BUS_A11: U1#1.M25(IO_L35N_1/A11)
BUS_A12: U1#1.AE26(IO_L02P_1/LDC1)
BUS_A13: U1#1.M26(IO_L35P_1/A10)
BUS_A14: U1#1.L24(IO_L38P_1/A12)
BUS_A15: U1#1.AB23(IO_L07P_1)
BUS_A16: U1#1.Y20(IO_L01P_1/HDC)
BUS_A17: U1#1.AB12(IO_L21P_2)
BUS_A18: U1#1.C17(IO_L19P_0)
BUS_A19: U1#1.B17(IO_L19N_0)
BUS_A20: U1#1.J26(IO_L43P_1/A18)
BUS_A21: U1#1.J22(IO_L49N_1)
BUS_A22: U1#1.L22(IO_L50P_1)
BUS_A23: U1#1.N24(IO_L33N_1/RHCLK5)
BUS_A24: U1#1.N21(IO_L37N_1)
BUS_D0: U1#1.P25(IO_L31N_1/TRDY1/RHCLK3)
BUS_D1: U1#1.R26(IO_L29N_1/A9)
BUS_D2: U1#1.R18(IO_L27P_1/A6)
BUS_D3: U1#1.R17(IO_L27N_1/A7)
BUS_D4: U1#1.T23(IO_L26P_1/A4)
BUS_D5: U1#1.U23(IO_L23P_1)
BUS_D6: U1#1.U24(IO_L23N_1/VREF_1)
BUS_D7: U1#1.G24(IO_L51N_1)
BUS_D8: U1#1.K26(IO_L41N_1)
BUS_D9: U1#1.T24(IO_L26N_1/A5)
BUS_D10: U1#1.R21(IO_L25P_1/A2)
BUS_D11: U1#1.R22(IO_L25N_1/A3)
BUS_D12: U1#1.R25(IO_L29P_1/A8)
BUS_D13: U1#1.P20(IO_L30N_1/RHCLK1)
BUS_D14: U1#1.P22(IO_L37P_1)
BUS_D15: U1#1.P26(IO_L31P_1/RHCLK2)
BUS_D16: U1#1.P18(IO_L34P_1/IRDY1/RHCLK6)
BUS_D17: U1#1.P6(IO_L39N_3)
BUS_D18: U1#1.T18(IO_L17P_1)
BUS_D19: U1#1.T17(IO_L17N_1)
BUS_D20: U1#1.U21(IO_L14P_1)
BUS_D21: U1#1.V23(IO_L21P_1)
BUS_D22: U1#1.V24(IO_L19P_1)
BUS_D23: U1#1.Y25(IO_L15N_1)
BUS_D24: U1#1.F25(IO_L54P_1)
BUS_D25: U1#1.U20(IO_L10N_1)
BUS_D26: U1#1.U22(IO_L21N_1)
BUS_D27: U1#1.T20(IO_L14N_1)
BUS_D28: U1#1.R19(IO_L22P_1)
BUS_D29: U1#1.R20(IO_L22N_1)
BUS_D30: U1#1.P21(IO_L30P_1/RHCLK0)
BUS_D31: U1#1.P23(IO_L33P_1/RHCLK4)
BUS_FLASH_NBUSY: U1#1.B26(IP_L65P_1/VREF_1) ; port MEM_COMMON.BUS_FLASH_NBUSY  [project net DB_MEM.BUS_FLASH_NBUSY]
BUS_FLASH_NCS: U1#1.C25(IO_L63N_1/A23) ; port MEM_COMMON.BUS_FLASH_NCS  [project net DB_MEM.BUS_FLASH_NCS]
BUS_FLASH_NRESET: U1#1.M19(IO_L47P_1) ; port MEM_COMMON.BUS_FLASH_NRESET  [project net DB_MEM.BUS_FLASH_NRESET]
BUS_ISP176X_DACK: U1#1.AF12(IO_L24P_2/D5) ; port ISP176X.BUS_DMA_ACK  [project net ISP176X.BUS_DMA_ACK]
BUS_ISP176X_DREQ: U1#1.AF17(IP_2/VREF_2) ; port ISP176X.BUS_DMA_REQ  [project net ISP176X.BUS_DMA_REQ]
BUS_ISP176X_NCS: U1#1.AA12(IO_L17N_2/VS2) ; port ISP176X.BUS_NCS  [project net ISP176X.BUS_NCS]
BUS_ISP176X_NIRQ: U1#1.AF15(IP_2/VREF_2) ; port ISP176X.BUS_NIRQ  [project net ISP176X.BUS_NIRQ]
BUS_NBE0: U1#1.U19(IO_L12P_1)
BUS_NBE1: U1#1.A22(IO_L07N_0)
BUS_NBE2: U1#1.AA25(IO_L11N_1)
BUS_NBE3: U1#1.V25(IO_L19N_1)
BUS_NOE: U1#1.AD11(IO_L23P_2) ; port MEM_COMMON.BUS_NOE, port ISP176X.BUS_NREAD  [project net DB_MEM.BUS_NOE]
BUS_NWE: U1#1.M3(IO_L27N_3) ; port MEM_COMMON.BUS_NWE, port ISP176X.BUS_NWRITE  [project net DB_MEM.BUS_NWE]
BUS_SDRAM_CKE: R274.2 R275.1 U1#1.V22(IO_L18N_1) ; port MEM_COMMON.BUS_SDRAM_CKE  [project net DB_MEM.BUS_SDRAM_CKE]
BUS_SDRAM_CLK: NT3#2.2(Net2) R272.2 R273.1 U1#1.F13(IO_L27P_0/GCLK8) ; port MEM_COMMON.BUS_SDRAM_CLK  [project net DB_MEM.BUS_SDRAM_CLK]
BUS_SDRAM_FEEDBACK: NT3#2.1(Net1) U1#1.AA14(IO_L27N_2/GCLK1)
BUS_SDRAM_NCAS: U1#1.AA24(IO_L11P_1) ; port MEM_COMMON.BUS_SDRAM_NCAS  [project net DB_MEM.BUS_SDRAM_NCAS]
BUS_SDRAM_NCS: U1#1.W20(IO_L04P_1) ; port MEM_COMMON.BUS_SDRAM_NCS  [project net DB_MEM.BUS_SDRAM_NCS]
BUS_SDRAM_NRAS: U1#1.AA22(IO_L09P_1) ; port MEM_COMMON.BUS_SDRAM_NRAS  [project net DB_MEM.BUS_SDRAM_NRAS]
BUS_SRAM_NCS: U1#1.D13(IO_L30P_0) ; port MEM_COMMON.BUS_SRAM_NCS  [project net DB_MEM.BUS_SRAM_NCS]
BUZZER: U1#1.P10(IO_L35N_3/LHCLK7) ; port BUZZER
CODECI2S_BCLK: U1#1.J14(IO_L25N_0/GCLK5) ; port CODEC.I2S_BCLK  [project net CODEC.I2S_BCLK]
CODECI2S_DIN: U1#1.T10(IO_L48P_3) ; port CODEC.I2S_DIN  [project net CODEC.I2S_DIN]
CODECI2S_DOUT: U1#1.AB4(IP_L62N_3) ; port CODEC.I2S_DOUT  [project net CODEC.I2S_DOUT]
CODECI2S_MCLK: U1#1.G13(IO_L27N_0/GCLK9) ; port CODEC.I2S_MCLK  [project net CODEC.I2S_MCLK]
CODECI2S_WCLK: U1#1.AF13(IO_L26P_2/GCLK14) ; port CODEC.I2S_WCLK  [project net CODEC.I2S_WCLK]
CODECSPI_CLK: U1#1.A14(IO_L26N_0/GCLK7) ; port CODEC.SPI_CLK  [project net CODEC.SPI_CLK]
CODECSPI_CS: U1#1.AE9(IO_L19P_2/VS1) ; port CODEC.SPI_CS_N  [project net CODEC.SPI_CS_N]
CODECSPI_DIN: U1#1.T4(IO_L38N_3) ; port CODEC.SPI_DIN  [project net CODEC.SPI_DIN]
CODECSPI_DOUT: U1#1.AE2(IP_L66N_3/VREF_3) ; port CODEC.SPI_DOUT  [project net CODEC.SPI_DOUT]
DAC_CLK: U1#1.C13(IO_L28N_0/GCLK11) ; port DAC.CLK  [project net DAC.CLK]
DAC_CS: U1#1.J7(IO_L10P_3) ; port DAC.CS  [project net DAC.CS]
DAC_DIN: U1#1.H2(IO_L17P_3) ; port DAC.DIN  [project net DAC.DIN]
DAU_FPGA_CLK1: U1#1.Y14(IO_L27P_2/GCLK0) ; port DB_CLOCKS.FPGA_CLK1  [project net DB_CLOCKS.FPGA_CLK1]
DAU_RESET_SW: U1#1.AD12(IP_2/VREF_2) ; port DAU_RESET_SW  [project net DB_RESET]
DAU_SPI_CLK: U1#1.AE14(IO_L28N_2/GCLK3) ; port DB_SPI.CLK  [project net DB_SPI.CLK]
DAU_SPI_DIN: U1#1.AD21(IO_L44N_2) ; port DB_SPI.DOUT  [project net DB_SPI.DOUT]
DAU_SPI_DOUT: U1#1.Y26(IP_L16N_1) ; port DB_SPI.DIN  [project net DB_SPI.DIN]
DAU_SPI_MODE: U1#1.AF25(IO_L51P_2) ; port DB_SPI.MODE  [project net DB_SPI.MODE]
DAU_SPI_SEL: U1#1.AE23(IO_L48N_2) ; port DB_SPI.SEL  [project net DB_SPI.SEL]
DIP0: U1#1.AD10(IP_2)
DIP1: U1#1.AC10(IP_2/VREF_2)
DIP2: U1#1.AB10(IP_2/VREF_2)
DIP3: U1#1.AD9(IP_2)
DIP4: U1#1.AF7(IP_2)
DIP5: U1#1.AA9(IP_2/VREF_2)
DIP6: U1#1.AC7(IP_2)
DIP7: U1#1.AB6(IP_2/VREF_2)
DONE: R22#1.2 ; sheet U_FPGA_Power/DONE
E_COL: U1#1.G1(IP_L16N_3) ; port ETH.E_COL  [project net ETH.E_COL]
E_CRS: U1#1.A5(IP_0) ; port ETH.E_CRS  [project net ETH.E_CRS]
E_MDC: U1#1.B2(IO_L02P_3) ; port ETH.E_MDC  [project net ETH.E_MDC]
E_MDIO: U1#1.D3(IO_L06P_3) ; port ETH.E_MDIO  [project net ETH.E_MDIO]
E_RESETB_E: U1#1.E4(IO_L06N_3) ; port ETH.E_RESETB_E  [project net ETH.E_RESETB_E]
E_RXC: U1#1.B14(IO_L26P_0/GCLK6) ; port ETH.E_RXC  [project net ETH.E_RXC]
E_RXD0: U1#1.C1(IP_L04N_3/VREF_3)
E_RXD1: U1#1.D2(IP_L08P_3)
E_RXD2: U1#1.D1(IP_L08N_3)
E_RXD3: U1#1.G5(IP_L12P_3)
E_RXDV: U1#1.C2(IP_L04P_3) ; port ETH.E_RXDV  [project net ETH.E_RXDV]
E_RXER: U1#1.A7(IP_0) ; port ETH.E_RXER  [project net ETH.E_RXER]
E_TXC: U1#1.H4(IP_L12N_3/VREF_3) ; port ETH.E_TXC  [project net ETH.E_TXC]
E_TXD0: U1#1.F4(IO_L07N_3)
E_TXD1: U1#1.E1(IO_L11P_3)
E_TXD2: U1#1.G6(IO_L03P_3)
E_TXD3: U1#1.F5(IO_L09P_3)
E_TXEN: U1#1.F3(IO_L14N_3) ; port ETH.E_TXEN  [project net ETH.E_TXEN]
EXTEND_A0: U1#1.AC6(IO_L08P_2)
EXTEND_A1: U1#1.AF10(IO_L22N_2/D6)
EXTEND_A2: U1#1.AF8(IO_L18N_2)
EXTEND_A3: U1#1.R6(IO_L40N_3)
EXTEND_A4: U1#1.AE8(IO_L18P_2)
EXTEND_A5: U1#1.AD7(IO_L11P_2)
EXTEND_A6: U1#1.AD6(IO_L08N_2)
EXTEND_A7: U1#1.AE7(IO_L11N_2)
EXTEND_A8: U1#1.AE6(IO_L10N_2)
EXTEND_A9: U1#1.AF5(IO_L10P_2)
EXTEND_A10: U1#1.AC2(IO_L64P_3)
EXTEND_A11: U1#1.AF4(IO_L07N_2)
EXTEND_A12: U1#1.AE4(IO_L07P_2)
EXTEND_A13: U1#1.AF3(IO_L06N_2)
EXTEND_A14: U1#1.AB1(IO_L60P_3)
EXTEND_A15: U1#1.AA7(IO_L02N_2/CSO_B)
EXTEND_A16: U1#1.Y5(IO_L57P_3)
EXTEND_A17: U1#1.AE3(IO_L06P_2)
EXTEND_A18: U1#1.AD2(IO_L65N_3)
EXTEND_A19: U1#1.AD1(IO_L65P_3)
EXTEND_A20: U1#1.AC3(IO_L64N_3)
EXTEND_A21: U1#1.AC1(IO_L60N_3)
EXTEND_A22: U1#1.AA2(IO_L55P_3)
EXTEND_A23: U1#1.Y6(IO_L57N_3)
EXTEND_A24: U1#1.W6(IO_L63N_3)
EXTEND_A25: U1#1.V8(IO_L61N_3)
EXTEND_A26: U1#1.AA3(IO_L55N_3)
EXTEND_A27: U1#1.Y2(IO_L53N_3)
EXTEND_A28: U1#1.Y1(IO_L53P_3)
EXTEND_A29: U1#1.W3(IO_L52P_3)
EXTEND_A30: U1#1.W4(IO_L52N_3)
EXTEND_A31: U1#1.V6(IO_L59N_3)
EXTEND_A32: U1#1.V7(IO_L59P_3)
EXTEND_A33: U1#1.U8(IO_L56N_3)
EXTEND_A34: U1#1.U9(IO_L61P_3)
EXTEND_A35: U1#1.V2(IO_L47N_3)
EXTEND_A36: U1#1.V1(IO_L47P_3)
EXTEND_A37: U1#1.U2(IO_L44N_3)
EXTEND_A38: U1#1.U1(IO_L44P_3)
EXTEND_A39: U1#1.U6(IO_L51N_3)
EXTEND_A40: U1#1.U5(IO_L49P_3)
EXTEND_A41: U1#1.T9(IO_L48N_3)
EXTEND_A42: U1#1.U4(IO_L42N_3)
EXTEND_A43: U1#1.T7(IO_L51P_3)
EXTEND_A44: U1#1.T3(IO_L38P_3)
EXTEND_A45: U1#1.T5(IO_L42P_3)
EXTEND_A46: U1#1.R8(IO_L45P_3)
EXTEND_A47: U1#1.R7(IO_L45N_3)
EXTEND_A48: U1#1.R3(IO_L37P_3)
EXTEND_A49: U1#1.R5(IO_L40P_3)
FPGA_CCLK: R20#1.1 ; port DB_PROGRAM.CCLK  [project net DB_PROGRAM.CCLK]
FPGA_CCLK#: R20#1.2 U1#1.AE24(IO_L52N_2/CCLK)
FPGA_CLK: U1#1.AE13(IO_L26N_2/GCLK15) ; port DB_CLOCKS.FPGA_CLK  [project net DB_CLOCKS.FPGA_CLK]
FPGA_DIN: U1#1.AF24(IO_L52P_2/D0/DIN/MISO) ; port DB_PROGRAM.DIN  [project net DB_PROGRAM.DIN]
FPGA_DONE: R4#1.1 R22#1.1 ; port STATUS_LED, port DB_PROGRAM.DONE  [project net DB_PROGRAM.DONE]
FPGA_ID0: NT2#2.1(Net1)
FPGA_ID1: NT3#3.1(Net1)
FPGA_ID2: NT4.1(Net1)
FPGA_ID3: NT5.1(Net1)
FPGA_INIT: R3#1.1 U1#1.AA15(IO_L34P_2/INIT_B) ; port DB_PROGRAM.INIT  [project net DB_PROGRAM.INIT]
FPGA_M0: R23#1.1
FPGA_M0#: R23#1.2 U1#1.AD4(IO_L01N_2/M0)
FPGA_M1: R18#1.1
FPGA_M1#: R18#1.2 U1#1.AC4(IO_L01P_2/M1)
FPGA_M2: R14#1.1
FPGA_M2#: R14#1.2 U1#1.Y7(IO_L02P_2/M2)
FPGA_PROGRAM: R1#1.1 R24#1.1 ; port DB_PROGRAM.PROGRAM  [project net DB_PROGRAM.PROGRAM]
FPGA_TCK: R9#1.1 ; harness JTAG.TCK
FPGA_TDI: R12#1.1 ; harness JTAG.TDI
FPGA_TDO: R2#1.1 R10#1.1 ; harness JTAG.TDO
FPGA_TMS: R8#1.1 ; harness JTAG.TMS
IO0: U1#1.M6(IO_L28N_3)
IO1: U1#1.N7(IO_L32N_3/LHCLK1)
IO2: U1#1.M8(IO_L26P_3)
IO3: U1#1.N6(IO_L32P_3/LHCLK0)
IO4: U1#1.L4(IO_L25P_3)
IO5: U1#1.M2(IO_L29P_3)
IO6: U1#1.L7(IO_L18N_3)
IO7: U1#1.M4(IO_L27P_3)
IO8: U1#1.K4(IO_L22N_3)
IO9: U1#1.M9(IO_L21N_3)
IO10: U1#1.K7(IO_L13P_3)
IO11: U1#1.M7(IO_L26N_3)
IO12: U1#1.K2(IO_L23N_3)
IO13: U1#1.M5(IO_L28P_3)
IO14: U1#1.K5(IO_L22P_3)
IO15: U1#1.M10(IO_L21P_3)
IO16: U1#1.K6(IO_L18P_3)
IO17: U1#1.L3(IO_L25N_3)
IO18: U1#1.J6(IO_L13N_3)
IO19: U1#1.K3(IO_L23P_3)
IO20: U1#1.J8(IO_L01P_3)
IO21: U1#1.K8(IO_L05N_3)
IO22: U1#1.H6(IO_L10N_3)
IO23: U1#1.J4(IO_L19N_3)
IO24: U1#1.G4(IO_L09N_3)
IO25: U1#1.J5(IO_L19P_3)
IO26: U1#1.P7(IO_L39P_3)
IO27: U1#1.H1(IO_L17N_3)
IO28: U1#1.N5(IO_L30P_3)
IO29: U1#1.N2(IO_L31N_3)
IO30: U1#1.N4(IO_L30N_3)
IO31: U1#1.N1(IO_L31P_3)
IO32: U1#1.P9(IO_L41N_3)
IO33: U1#1.P4(IO_L34P_3/LHCLK4)
IO34: U1#1.R4(IO_L37N_3)
IO35: U1#1.R10(IO_L43P_3/VREF_3)
IR38KRX: U1#1.W13(IO_L20N_2) ; port TFT_IO.IR38KRX  [project net TFT_IO.IR38KRX]
IR38KTX: U1#1.Y12(IO_L17P_2/RDWR_B) ; port TFT_IO.IR38KTX  [project net TFT_IO.IR38KTX]
ISP176X_RST: U1#1.AF9(IO_L19N_2/VS0) ; port ISP176X.ISP176X_NRESET  [project net ISP176X.ISP176X_NRESET]
KBCLOCK: U1#1.AB7(IO_L14N_2) ; port KEYBOARD.CLOCK  [project net KEYBOARD.CLOCK]
KBDATA: U1#1.AC8(IO_L14P_2) ; port KEYBOARD.DATA  [project net KEYBOARD.DATA]
LED0_B: U1#1.P2(IO_L33N_3/IRDY2/LHCLK3) ; harness RGB_LED.BLUE
LED0_G: U1#1.R1(IO_L36P_3/VREF_3) ; harness RGB_LED.GREEN
LED0_R: U1#1.P1(IO_L33P_3/LHCLK2) ; harness RGB_LED.RED
LED1_B: U1#1.P8(IO_L41P_3) ; harness RGB_LED.BLUE
LED1_G: U1#1.P3(IO_L34N_3/LHCLK5) ; harness RGB_LED.GREEN
LED1_R: U1#1.R9(IO_L43N_3) ; harness RGB_LED.RED
LED2_B: U1#1.AA10(IO_L12N_2) ; harness RGB_LED.BLUE
LED2_G: U1#1.AE10(IO_L22P_2/D7) ; harness RGB_LED.GREEN
LED2_R: U1#1.AC9(IO_L15N_2) ; harness RGB_LED.RED
LED3_B: U1#1.AC11(IO_L23N_2) ; harness RGB_LED.BLUE
LED3_G: U1#1.W12(IO_L16N_2) ; harness RGB_LED.GREEN
LED3_R: U1#1.V11(IO_L13P_2) ; harness RGB_LED.RED
LED4_B: U1#1.AA23(IO_L09N_1) ; harness RGB_LED.BLUE
LED4_G: U1#1.AC25(IO_L05N_1) ; harness RGB_LED.GREEN
LED4_R: U1#1.Y21(IO_L01N_1/LDC2) ; harness RGB_LED.RED
LED5_B: U1#1.AC26(IO_L06P_1) ; harness RGB_LED.BLUE
LED5_G: U1#1.W21(IO_L04N_1) ; harness RGB_LED.GREEN
LED5_R: U1#1.Y22(IO_L13P_1) ; harness RGB_LED.RED
LED6_B: U1#1.W23(IO_L18P_1) ; harness RGB_LED.BLUE
LED6_G: U1#1.Y23(IO_L13N_1) ; harness RGB_LED.GREEN
LED6_R: U1#1.V21(IO_L10P_1) ; harness RGB_LED.RED
LED7_B: U1#1.AB24(IO_L07N_1/VREF_1) ; harness RGB_LED.BLUE
LED7_G: U1#1.Y24(IO_L15P_1) ; harness RGB_LED.GREEN
LED7_R: U1#1.V19(IO_L08N_1) ; harness RGB_LED.RED
MIDI_RX: U1#1.C4(IP_0) ; port MIDI.MIDI_RX  [project net MIDI.MIDI_RX]
MIDI_TX: U1#1.H7(IO_L03N_3) ; port MIDI.MIDI_TX  [project net MIDI.MIDI_TX]
MOUSECLOCK: U1#1.AB9(IO_L15P_2) ; port MOUSE.CLOCK  [project net MOUSE.CLOCK]
MOUSEDATA: U1#1.W7(IO_L63P_3) ; port MOUSE.DATA  [project net MOUSE.DATA]
NEXUS_TCK: U1#1.AF14(IO_L28P_2/GCLK2) ; harness JTAG.TCK
NEXUS_TDI: U1#1.AA19(IP_2) ; harness JTAG.TDI
NEXUS_TDO: U1#1.AC20(IO_L41N_2) ; harness JTAG.TDO
NEXUS_TMS: U1#1.AB20(IP_2) ; harness JTAG.TMS
ONE_WIRE_DB_PB: R283.2 U1#1.R2(IO_L36N_3) ; port ONE_WIRE_DB_PB
P0_PWM: U1#1.C7(IO_L42N_0) ; port PWM.PWM0  [project net PWM.PWM0]
P1_PWM: U1#1.B6(IO_L41P_0) ; port PWM.PWM1  [project net PWM.PWM1]
P2_PWM: U1#1.A4(IO_L45P_0) ; port PWM.PWM2  [project net PWM.PWM2]
P3_PWM: U1#1.B4(IO_L45N_0) ; port PWM.PWM3  [project net PWM.PWM3]
PROG_B: R24#1.2 ; sheet U_FPGA_Power/PROG_B
REF_CLK: U1#1.K14(IO_L25P_0/GCLK4) ; port DB_CLOCKS.REF_CLK  [project net DB_CLOCKS.REF_CLK]
RELAY0: U1#1.C6(IO_L41N_0)
RELAY1: U1#1.C10(IO_L34P_0)
RELAY2: U1#1.C12(IO_L30N_0)
RELAY3: U1#1.B12(IO_L29N_0)
RS232_CTS: U1#1.J2(IP_L20N_3/VREF_3) ; port RS232.CTS  [project net RS232.CTS]
RS232_RTS: U1#1.E3(IO_L07P_3) ; port RS232.RTS  [project net RS232.RTS]
RS232_RX: U1#1.G2(IP_L16P_3) ; port RS232.RXD  [project net RS232.RXD]
RS232_TX: U1#1.B1(IO_L02N_3) ; port RS232.TXD  [project net RS232.TXD]
SCL: R277.2 U1#1.V5(IO_L49N_3) ; port I2C.SCL  [project net I2C.SCL]
SDA: R278.1 U1#1.U7(IO_L56P_3) ; port I2C.SDA  [project net I2C.SDA]
SDCLK: U1#1.AA13(IO_L25P_2/GCLK12) ; port DBSD.CLK  [project net DBSD.CLK]
SDCMD: U1#1.V12(IO_L16P_2) ; port DBSD.CMD  [project net DBSD.CMD]
SDDAT0: U1#1.V16(IO_L42P_2)
SDDAT1: U1#1.V18(IO_L08P_1)
SDDAT2: U1#1.V13(IO_L20P_2)
SDDAT3: U1#1.U11(IO_L13N_2)
SDDETECT: U1#1.AC13(IP_2) ; port DBSD.DETECT  [project net DBSD.DETECT]
SDPROTECT: U1#1.AB13(IP_2) ; port DBSD.PROTECT  [project net DBSD.PROTECT]
SPAREIO1: U1#1.W9(IO_L05P_2) ; port SPAREIO.1  [project net SPAREIO.1]
SPAREIO2: U1#1.W10(IO_L09N_2) ; port SPAREIO.2  [project net SPAREIO.2]
SPAREIO3: U1#1.Y9(IO_L05N_2) ; port SPAREIO.3  [project net SPAREIO.3]
SPAREIO4: U1#1.Y10(IO_L12P_2) ; port SPAREIO.4  [project net SPAREIO.4]
SPDIF_IN: U1#1.AF2(IP_2) ; port SPDIF.IN  [project net SPDIF.IN]
SPDIF_OUT: U1#1.V10(IO_L09P_2) ; port SPDIF.OUT  [project net SPDIF.OUT]
SRAM1_A0: U1#1.J12(IO_L39P_0)
SRAM1_A1: U1#1.F14(IO_L24N_0)
SRAM1_A2: U1#1.F15(IO_L20P_0)
SRAM1_A3: U1#1.G17(IO_L08N_0)
SRAM1_A4: U1#1.B19(IO_L15P_0)
SRAM1_A5: U1#1.K21(IO_L50N_1)
SRAM1_A6: U1#1.K23(IO_L46P_1)
SRAM1_A7: U1#1.L9(IO_L15N_3)
SRAM1_A8: U1#1.M18(IO_L47N_1)
SRAM1_A9: U1#1.N9(IO_L35P_3/TRDY2/LHCLK6)
SRAM1_A10: U1#1.M20(IO_L42N_1/A17)
SRAM1_A11: U1#1.L18(IO_L55P_1)
SRAM1_A12: U1#1.L17(IO_L55N_1)
SRAM1_A13: U1#1.J23(IO_L49P_1)
SRAM1_A14: U1#1.J19(IO_L59P_1)
SRAM1_A15: U1#1.B15(IO_L23P_0)
SRAM1_A16: U1#1.G12(IO_L35P_0)
SRAM1_A17: U1#1.F12(IO_L31N_0)
SRAM1_A18: U1#1.H21(IO_L62N_1/A21)
SRAM1_D0: U1#1.D21(IO_L10N_0)
SRAM1_D1: U1#1.B23(IO_L07P_0)
SRAM1_D2: U1#1.C21(IO_L09P_0)
SRAM1_D3: U1#1.D17(IO_L21P_0)
SRAM1_D4: U1#1.C26(IO_L63P_1/A22)
SRAM1_D5: U1#1.G20(IO_L01P_0)
SRAM1_D6: U1#1.F22(IO_L58P_1/VREF_1)
SRAM1_D7: U1#1.G22(IO_L58N_1)
SRAM1_D8: U1#1.G21(IO_L64N_1/A25)
SRAM1_D9: U1#1.E26(IO_L60P_1)
SRAM1_D10: U1#1.D26(IO_L60N_1)
SRAM1_D11: U1#1.D24(IO_L61N_1)
SRAM1_D12: U1#1.H10(IO_L46N_0)
SRAM1_D13: U1#1.B18(IO_L18P_0)
SRAM1_D14: U1#1.E21(IO_L10P_0)
SRAM1_D15: U1#1.F19(IO_L02N_0)
SRAM1_NBHE: U1#1.G15(IO_L16P_0) ; port SRAM1.NBHE  [project net DB_SRAM1.NBHE]
SRAM1_NBLE: U1#1.E17(IO_L13N_0) ; port SRAM1.NBLE  [project net DB_SRAM1.NBLE]
SRAM1_NCS: U1#1.C20(IO_L11N_0) ; port SRAM1.NCS  [project net DB_SRAM1.NCS]
SRAM1_NOE: U1#1.E14(IO_L24P_0) ; port SRAM1.NOE  [project net DB_SRAM1.NOE]
SRAM1_NWE: U1#1.J20(IO_L59N_1) ; port SRAM1.NWE  [project net DB_SRAM1.NWE]
SRAM2_A0: U1#1.D16(IO_L22P_0)
SRAM2_A1: U1#1.D18(IO_L17P_0)
SRAM2_A2: U1#1.A20(IO_L14N_0)
SRAM2_A3: U1#1.D20(IO_L11P_0)
SRAM2_A4: U1#1.F20(IO_L01N_0)
SRAM2_A5: U1#1.K18(IO_L57N_1)
SRAM2_A6: U1#1.M22(IO_L45N_1)
SRAM2_A7: U1#1.N19(IO_L34N_1/RHCLK7)
SRAM2_A8: U1#1.N17(IO_L39N_1/A15)
SRAM2_A9: U1#1.N18(IO_L39P_1/A14)
SRAM2_A10: U1#1.N20(IO_L42P_1/A16)
SRAM2_A11: U1#1.M23(IO_L38N_1/A13)
SRAM2_A12: U1#1.M21(IO_L45P_1)
SRAM2_A13: U1#1.L20(IO_L53P_1)
SRAM2_A14: U1#1.K22(IO_L46N_1)
SRAM2_A15: U1#1.F17(IO_L13P_0)
SRAM2_A16: U1#1.H15(IO_L16N_0)
SRAM2_A17: U1#1.E15(IO_L20N_0/VREF_0)
SRAM2_A18: U1#1.K19(IO_L57P_1)
SRAM2_D0: U1#1.J16(IO_L12P_0)
SRAM2_D1: U1#1.G19(IO_L02P_0/VREF_0)
SRAM2_D2: U1#1.C23(IO_L06N_0)
SRAM2_D3: U1#1.H17(IO_L08P_0)
SRAM2_D4: U1#1.K16(IO_L12N_0)
SRAM2_D5: U1#1.H20(IO_L64P_1/A24)
SRAM2_D6: U1#1.F23(IO_L56N_1)
SRAM2_D7: U1#1.K9(IO_L05P_3)
SRAM2_D8: U1#1.G23(IO_L51P_1)
SRAM2_D9: U1#1.F24(IO_L54N_1)
SRAM2_D10: U1#1.E24(IO_L56P_1)
SRAM2_D11: U1#1.D25(IO_L61P_1)
SRAM2_D12: U1#1.A18(IO_L18N_0)
SRAM2_D13: U1#1.C22(IO_L05N_0)
SRAM2_D14: U1#1.D23(IO_L06P_0)
SRAM2_D15: U1#1.D22(IO_L05P_0)
SRAM2_NBHE: U1#1.B20(IO_L14P_0/VREF_0) ; port SRAM2.NBHE  [project net DB_SRAM2.NBHE]
SRAM2_NBLE: U1#1.B21(IO_L09N_0) ; port SRAM2.NBLE  [project net DB_SRAM2.NBLE]
SRAM2_NCS: U1#1.K11(IO_L43N_0) ; port SRAM2.NCS  [project net DB_SRAM2.NCS]
SRAM2_NOE: U1#1.A19(IO_L15N_0) ; port SRAM2.NOE  [project net DB_SRAM2.NOE]
SRAM2_NWE: U1#1.K20(IO_L53N_1) ; port SRAM2.NWE  [project net DB_SRAM2.NWE]
SW0: U1#1.K1(IP_L24N_3)
SW1: U1#1.U3(IP_L46P_3)
SW2: U1#1.W2(IP_L50N_3/VREF_3)
SW3: U1#1.V4(IP_L46N_3)
SW4: U1#1.W1(IP_L50P_3)
TCK: R9#1.2 ; sheet U_FPGA_Power/TCK
TDI: R12#1.2 ; sheet U_FPGA_Power/TDI
TDO: R10#1.2 ; sheet U_FPGA_Power/TDO
TFT_BLIGHT: U1#1.AC23(IO_L03P_1/A0) ; port TFT_IO.BL  [project net TFT_IO.BL]
TFT_CS: U1#1.AC16(IO_L38P_2) ; port TFT_IO.CS  [project net TFT_IO.CS]
TFT_DB0: U1#1.AD14(IO_L29P_2)
TFT_DB1: U1#1.AB15(IO_L30N_2/MOSI/CSI_B)
TFT_DB2: U1#1.AE12(IO_L24N_2/D4)
TFT_DB3: U1#1.AE15(IO_L32N_2/DOUT)
TFT_DB4: U1#1.AF23(IO_L48P_2)
TFT_DB5: U1#1.AC15(IO_L30P_2)
TFT_DB6: U1#1.AC14(IO_L29N_2)
TFT_DB7: U1#1.AC12(IO_L21N_2)
TFT_DB10: U1#1.AC21(IO_L45N_2)
TFT_DB11: U1#1.AD22(IO_L45P_2)
TFT_DB12: U1#1.AC19(IO_L40N_2)
TFT_DB13: U1#1.Y17(IO_L43N_2)
TFT_DB14: U1#1.AD19(IO_L40P_2)
TFT_DB15: U1#1.W17(IO_L46P_2)
TFT_DB16: U1#1.AB16(IO_L38N_2)
TFT_DB17: U1#1.W15(IO_L31N_2)
TFT_RD: U1#1.AD20(IO_L41P_2) ; port TFT_IO.RD  [project net TFT_IO.RD]
TFT_RESET: U1#1.V15(IO_L35P_2) ; port TFT_IO.RESET  [project net TFT_IO.RESET]
TFT_RS: U1#1.AF18(IO_L36P_2/D2) ; port TFT_IO.RS  [project net TFT_IO.RS]
TFT_TSC_BUSY: U1#1.W26(IP_L20P_1) ; port TFT_TSC.BUSY  [project net TFT_TSC.BUSY]
TFT_TSC_CLK: U1#1.Y13(IO_L25N_2/GCLK13) ; port TFT_TSC.CLK  [project net TFT_TSC.CLK]
TFT_TSC_CS_N: U1#1.AB26(IO_L06N_1) ; port TFT_TSC.CS_N  [project net TFT_TSC.CS_N]
TFT_TSC_DIN: U1#1.AD26(IO_L05P_1) ; port TFT_TSC.DIN  [project net TFT_TSC.DIN]
TFT_TSC_DOUT: U1#1.W25(IP_L16P_1) ; port TFT_TSC.DOUT  [project net TFT_TSC.DOUT]
TFT_TSC_IRQ_N: U1#1.AE25(IO_L51N_2) ; port TFT_TSC.TFT_INT  [project net TFT_TSC.TFT_INT]
TFT_WR: U1#1.AE18(IO_L36N_2/D1) ; port TFT_IO.WR  [project net TFT_IO.WR]
TMS: R8#1.2 ; sheet U_FPGA_Power/TMS
USB_D0: U1#1.AE17(IO_L33P_2)  [project net HUSB_D0]
USB_D1: U1#1.U15(IO_L35N_2)  [project net HUSB_D1]
USB_D2: U1#1.AD17(IO_L33N_2)  [project net HUSB_D2]
USB_D3: U1#1.Y15(IO_L34N_2/D3)  [project net HUSB_D3]
USB_D4: U1#1.AC24(IO_L03N_1/A1)  [project net HUSB_D4]
USB_D5: U1#1.AF19(IO_L37P_2)  [project net HUSB_D5]
USB_D6: U1#1.AE19(IO_L37N_2)  [project net HUSB_D6]
USB_D7: U1#1.AF20(IO_L39P_2)  [project net HUSB_D7]
USB_FIFOADR0: U1#1.AA17(IO_L43P_2) ; port DBUSB.FIFOADR0  [project net DBUSB.FIFOADR0]
USB_FIFOADR1: U1#1.AD25(IO_L02N_1/LDC0) ; port DBUSB.FIFOADR1  [project net DBUSB.FIFOADR1]
USB_FIFOADR2: U1#1.AA18(IO_L47N_2) ; port DBUSB.FIFOADR2  [project net DBUSB.FIFOADR2]
USB_FLAGA: U1#1.AC17(IP_2) ; port DBUSB.FLAGA  [project net DBUSB.FLAGA]
USB_FLAGB: U1#1.AB17(IP_2) ; port DBUSB.FLAGB  [project net DBUSB.FLAGB]
USB_FLAGC: U1#1.AA20(IP_2/VREF_2) ; port DBUSB.FLAGC  [project net DBUSB.FLAGC]
USB_FLAGD_CS_N: U1#1.AE20(IO_L39N_2) ; port DBUSB.FLAGD_CS_N  [project net DBUSB.FLAGD_CS_N]
USB_IFCLK: U1#1.V14(IO_L31P_2) ; port DBUSB.IFCLK  [project net DBUSB.IFCLK]
USB_INT_N: U1#1.AF22(IP_2/VREF_2) ; port DBUSB.INT_N  [project net DBUSB.INT_N]
USB_PKTEND: U1#1.AE21(IO_L44P_2) ; port DBUSB.PKTEND  [project net DBUSB.PKTEND]
USB_RD_N: U1#1.U16(IO_L42N_2) ; port DBUSB.RD_N  [project net DBUSB.RD_N]
USB_READY: U1#1.R24(IP_L28N_1) ; port DBUSB.READY  [project net DBUSB.READY]
USB_RESET_N: U1#1.V17(IO_L46N_2) ; port DBUSB.RESET_N  [project net DBUSB.RESET_N]
USB_SLOE: U1#1.AB18(IO_L47P_2) ; port DBUSB.SLOE  [project net DBUSB.SLOE]
USB_VBUS: U1#1.AC18(IP_2) ; port DBUSB.VBUS  [project net DBUSB.VBUS]
USB_WR_N: U1#1.U18(IO_L12N_1) ; port DBUSB.WR_N  [project net DBUSB.WR_N]
VGA_BLUE0: U1#1.K12(IO_L39N_0)
VGA_BLUE1: U1#1.D11(IO_L32N_0/VREF_0)
VGA_BLUE2: U1#1.J11(IO_L43P_0)
VGA_BLUE3: U1#1.A10(IO_L33P_0)
VGA_BLUE4: U1#1.B10(IO_L33N_0)
VGA_BLUE5: U1#1.D10(IO_L34N_0)
VGA_BLUE6: U1#1.G10(IO_L46P_0)
VGA_BLUE7: U1#1.E10(IO_L37P_0)
VGA_CLK: U1#1.C5(IO_L44P_0) ; port VGA.VGA_CLK  [project net VGA.VGA_CLK]
VGA_GREEN0: U1#1.D8(IO_L40N_0)
VGA_GREEN1: U1#1.C8(IO_L40P_0)
VGA_GREEN2: U1#1.F8(IO_L52P_0/VREF_0)
VGA_GREEN3: U1#1.B7(IO_L42P_0)
VGA_GREEN4: U1#1.E7(IO_L48N_0)
VGA_GREEN5: U1#1.F7(IO_L48P_0)
VGA_GREEN6: U1#1.D6(IO_L44N_0)
VGA_GREEN7: U1#1.G8(IO_L52N_0/PUDC_B)
VGA_HSYNC: U1#1.C11(IO_L32P_0) ; port VGA.VGA_HSYNC  [project net VGA#.HSYNC]
VGA_RED0: U1#1.A9(IO_L36P_0)
VGA_RED1: U1#1.B9(IO_L36N_0)
VGA_RED2: U1#1.D9(IO_L37N_0)
VGA_RED3: U1#1.G9(IO_L47P_0)
VGA_RED4: U1#1.A8(IO_L38P_0)
VGA_RED5: U1#1.J9(IO_L01N_3)
VGA_RED6: U1#1.H9(IO_L47N_0)
VGA_RED7: U1#1.B8(IO_L38N_0)
VGA_VSYNC: U1#1.H12(IO_L35N_0) ; port VGA.VGA_VSYNC  [project net VGA#.VSYNC]

Not connected (* = marked no-connect by the designer): U1#1 A13(IP_0)* A17(IP_0)* A23(IP_0)* AA4(IP_L58P_3)* AA5(IP_L58N_3/VREF_3)* AB3(IP_L62P_3)* AD16(IP_2)* AE1(IP_L66P_3)* B25(IP_L65N_1)* D12(IP_0)* D14(IP_0/VREF_0)* D15(IP_0)* D19(IP_0)* E11(IP_0)* E12(IO_L31P_0)* E18(IP_0)* E20(IP_0)* F10(IP_0)* G11(IP_0/VREF_0)* G14(IP_0)* G16(IP_0)* G25(IP_L52N_1/VREF_1)* G26(IP_L52P_1)* H13(IP_0)* H18(IP_0)* H23(IP_L48P_1)* H24(IP_L48N_1)* H25(IP_L44N_1)* H26(IP_L44P_1/VREF_1)* J3(IP_L20P_3)* J10(IP_0)* J13(IP_0)* J15(IP_0)* J17(IP_0/VREF_0)* K24(IP_L40P_1)* L23(IP_L40N_1)* M24(IP_L36P_1/VREF_1)* N23(IP_L36N_1)* N25(IP_L32N_1)* N26(IP_L32P_1)* R23(IP_L28P_1/VREF_1)* U25(IP_L24P_1)* U26(IP_L24N_1/VREF_1)* V26(IP_L20N_1/VREF_1)* Y3(IP_L54P_3)* Y4(IP_L54N_3)* Y11(IP_2)* Y16(IP_2/VREF_2)*

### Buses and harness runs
bus BUS_A[17..1]
bus BUS_A[24..1]
bus BUS_D[31..0]
bus BUS_NBE[3..0]
bus DIP[7..0]
bus E_RXD[3..0]
bus E_TXD[3..0]
bus EXTEND_A[49..0]
bus FPGA_ID[3..0]
bus FPGA_M[2..0]
bus IO[35..0]
bus RELAY[3..0]
bus SDDAT[3..0]
bus SRAM1_A[18..0]
bus SRAM1_D[15..0]
bus SRAM2_A[18..0]
bus SRAM2_D[15..0]
bus SW[4..0]
bus TFT_DB[17..0]
bus USB_D[15..0]
bus VGA_BLUE[7..0]
bus VGA_GREEN[7..0]
bus VGA_RED[7..0]

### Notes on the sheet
- USER/DB FPGA
- JTAG
- PROGRAM
- SPI
- CLOCKS
- COMMON MEMORY RESOURCES
- USB2
- (near NT3#2) STANDALON MEMORY RESOURCES
- 24MHz provided on top level schematic
- PERIPHERALS
- (near R4#1) 1V2
- 3V3
- FPGA_ID = 0x4

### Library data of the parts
NT2#2 NT3#2 NT3#3 NT4 NT5 = D-002-0002: Net-Tie, Surface Mount, 2 x 0.4mm x 0.2mm SMT Pads - For 0.2mm Track
R1#1 R2#1 R3#1 R4#1 R277 R278 R283 = D-100-0088: Resistor, 4K7 1% 0402 (1005); Power Rating: 63 mW; Resistance: 4.7 K
R8#1 R9#1 R10#1 R12#1 R14#1 R18#1 R20#1 R22#1 R23#1 R24#1 = D-100-0131: Resistor, 100R 1% 0402 (1005); Power Rating: 63 mW
R272-R275 = D-100-0107: Resistor, 2K2 1% 0402 (1005); Power Rating: 63 mW; Resistance: 2.2 K
U1#1 = D-241-0015: FPGA, Xilinx Spartan 3AN-1400 FG676; Supply Voltage: mV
